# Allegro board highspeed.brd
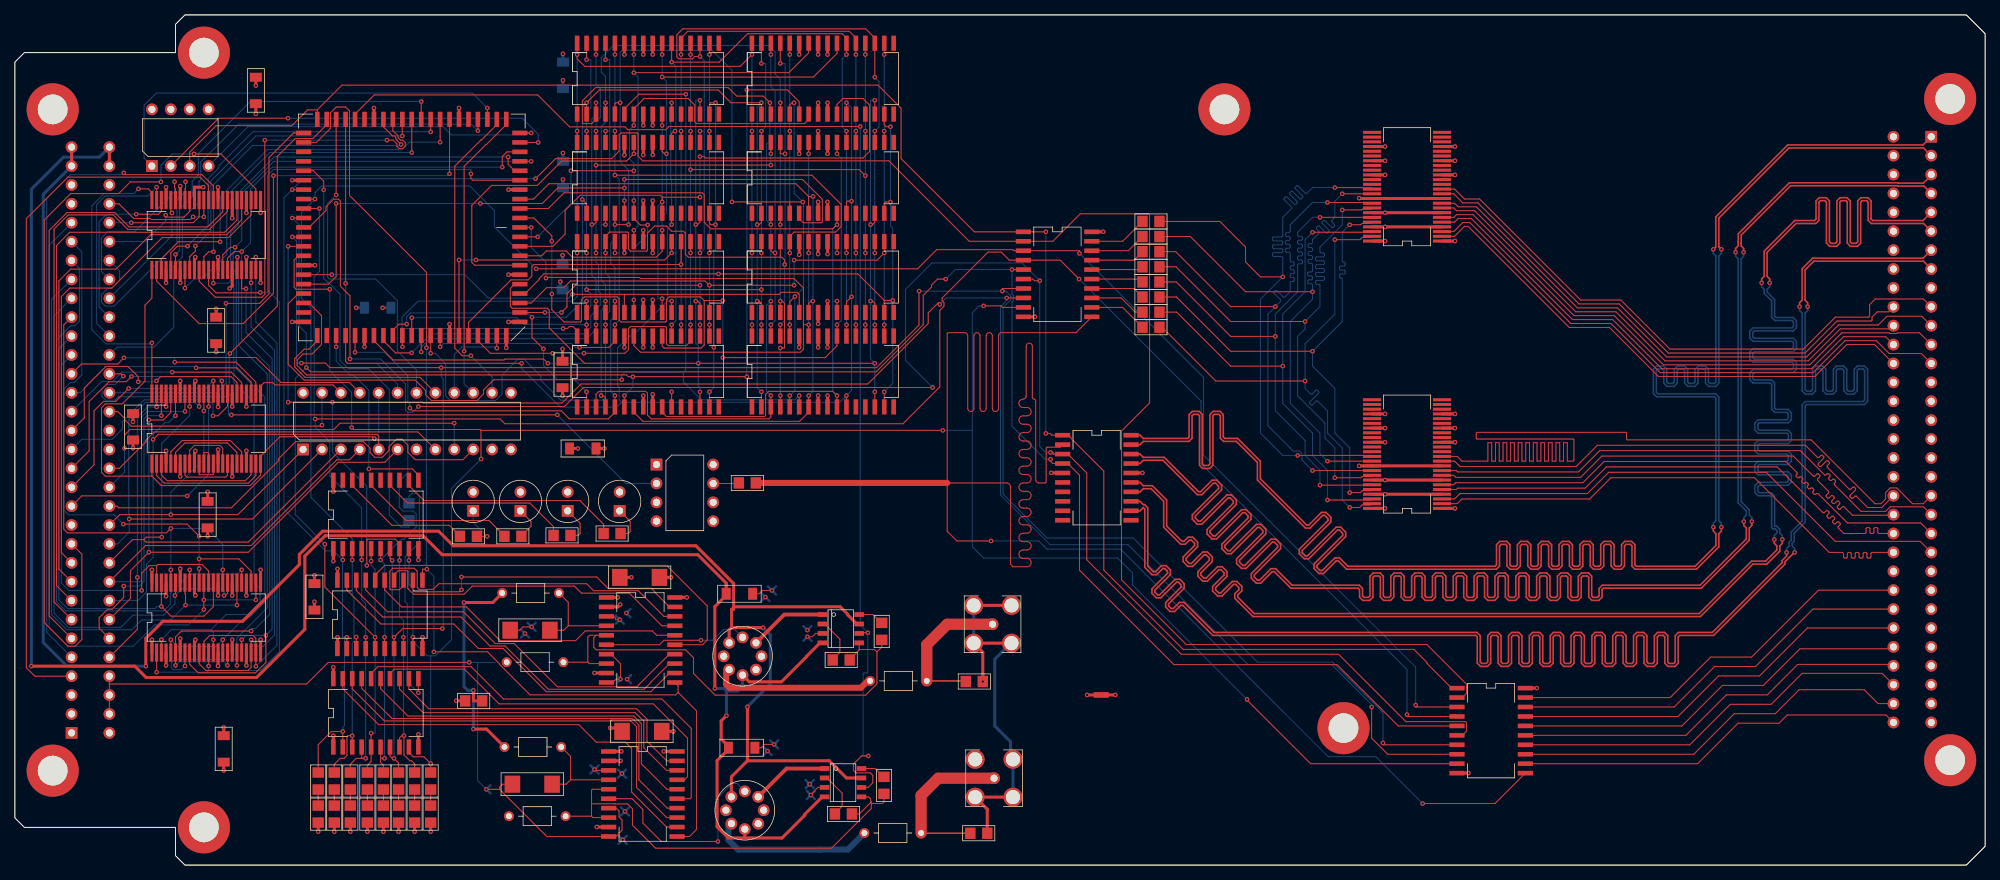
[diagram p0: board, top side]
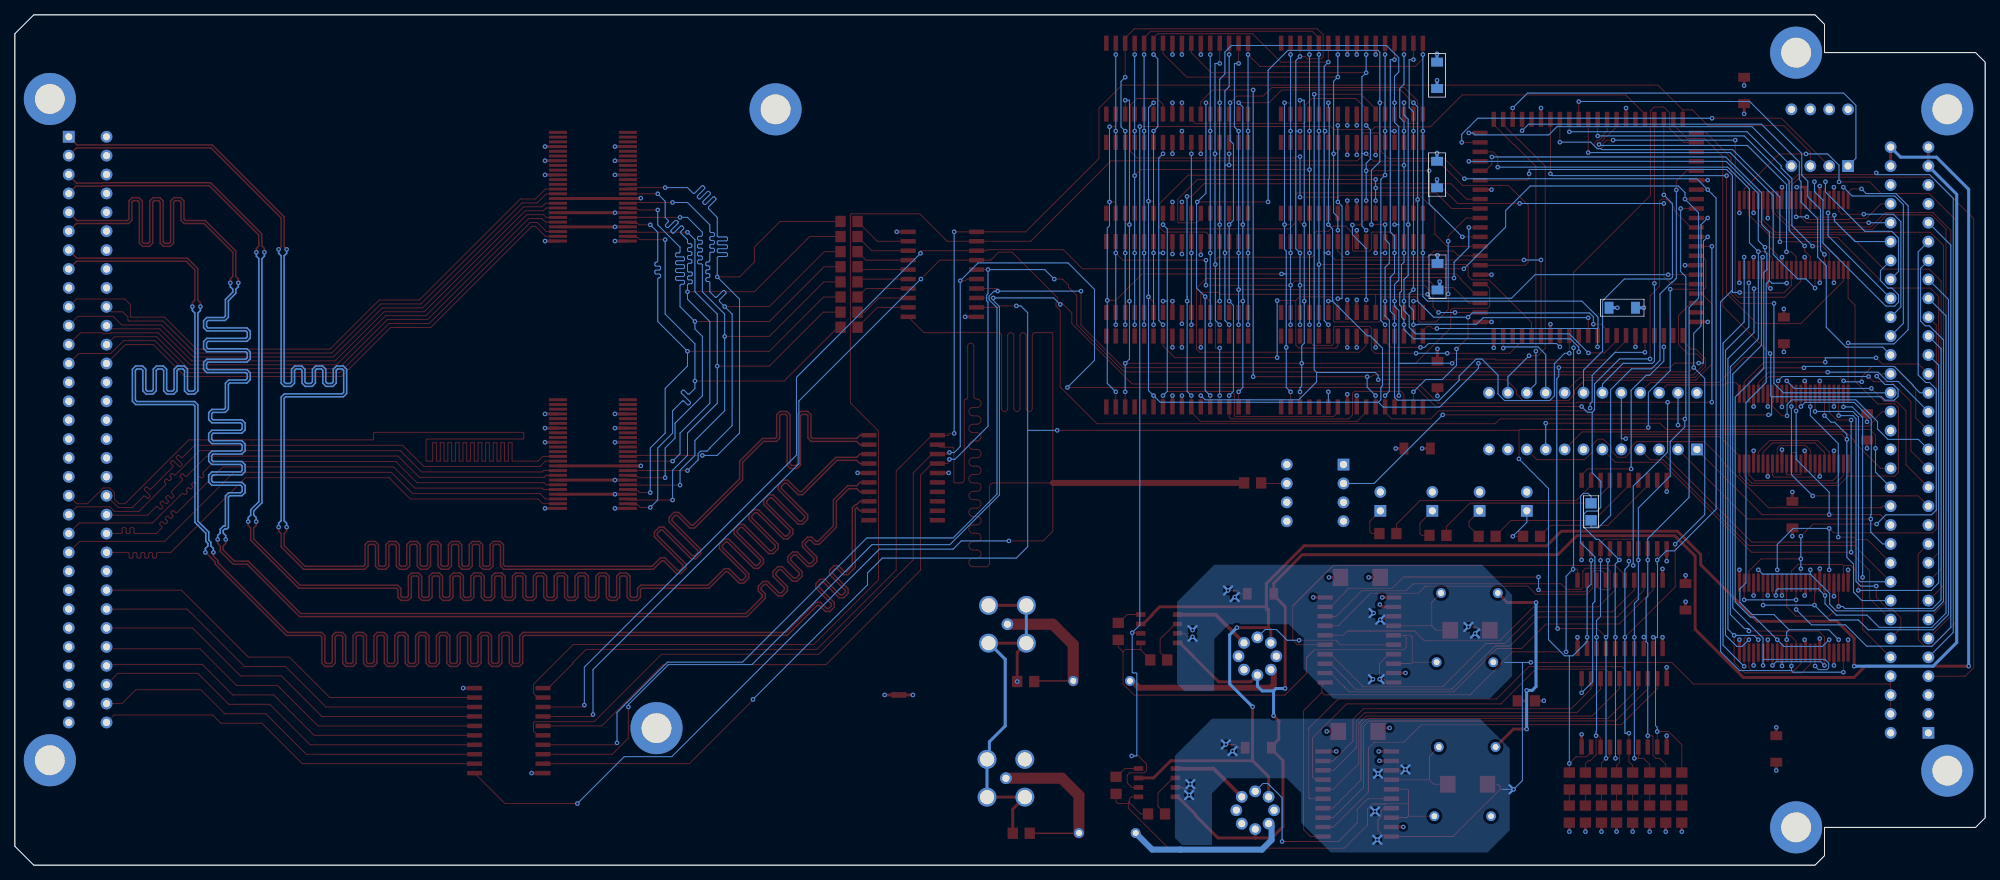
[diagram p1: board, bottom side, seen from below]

Outline 264.8 x 114.3 mm; copper layers: TOP, GND, VCC, BOTTOM. Coordinates in mm from the lower left corner of the outline.

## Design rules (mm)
constraint set DEFAULT: min track width 0.127
net group Q0: nets Q0 Q1
net group Q2: nets Q2 Q3
net group Q4: nets Q4 Q5
net group Q6: nets Q6 Q7
net group VD<0>: nets UNNAMED_1_CAP_I74_A VD<0>
net group VD<1>: nets UNNAMED_1_CAP_I73_A VD<1>
net group VD<2>: nets UNNAMED_1_CAP_I72_A VD<2>
net group VD<3>: nets UNNAMED_1_CAP_I71_A VD<3>
net group VD<4>: nets UNNAMED_1_CAP_I70_A VD<4>
net group VD<5>: nets UNNAMED_1_CAP_I69_A VD<5>
net group VD<6>: nets UNNAMED_1_CAP_I68_A VD<6>
net group VD<7>: nets UNNAMED_1_CAP_I67_A VD<7>
net group VREF: nets UNNAMED_1_CAP_I33_A_1 UNNAMED_1_CAP_I33_A_2
net group A: nets A<0> A<1> A<2> A<3> A<4> A<5> A<6> A<7> A<8> A<9> A<10> A<11> A<12> A<13> A<14> A<15> A<16> A<17> A<18> A<19> A<20> A<21> A<22> A<23>
net group BA: nets BA<0> BA<1> BA<2> BA<3> BA<4> BA<5> BA<6> BA<7>
net group BD: nets BD<0> BD<1> BD<2> BD<3> BD<4> BD<5> BD<6> BD<7> BD<8> BD<9> BD<10> BD<11> BD<12> BD<13> BD<14> BD<15>
net group BR: nets BR<0> BR<1> BR<2> BR<3> BR<4> BR<5> BR<6> BR<7>
net group CLOCKS: nets CLK1_N CLK2_N CLK3_N CLK4_N DCLK MCLK UNNAMED_2_EPF8282A_I1_VCLKC VCLKA VCLKC
net group D: nets D<0> D<1> D<2> D<3> D<4> D<5> D<6> D<7> D<8> D<9> D<10> D<11> D<12> D<13> D<14> D<15>
net group DP_CLK1: nets CLK1_P
net group DP_CLK2: nets CLK2_P
net group DP_CLK3: nets CLK3_P
net group DP_CLK4: nets CLK4_P
net group IO<0>: nets UNNAMED_3_ACT574_I6_Q0
net group IO<1>: nets UNNAMED_3_ACT574_I6_Q1
net group IO<2>: nets UNNAMED_3_ACT574_I6_Q2
net group IO<3>: nets UNNAMED_3_ACT574_I6_Q3
net group IO<4>: nets UNNAMED_3_ACT574_I6_Q4
net group IO<5>: nets UNNAMED_3_ACT574_I6_Q5
net group IO<6>: nets UNNAMED_3_ACT574_I6_Q6
net group IO<7>: nets UNNAMED_3_ACT574_I6_Q7
net group IOA: nets IOA<0> IOA<1> IOA<2> IOA<3> IOA<4> IOA<5> IOA<6> IOA<7>
net group IOB: nets IOB<0> IOB<1> IOB<2> IOB<3> IOB<4> IOB<5> IOB<6> IOB<7>
net group POWER: nets GND V12N V+12 VCC VREF
net group RA: nets RA<0> RA<1> RA<2> RA<3> RA<4> RA<5> RA<6> RA<7> RA<8> RA<9> RA<10> RA<11> RA<12> RA<13> RA<14> RA<15>
net group RD: nets RD<0> RD<1> RD<2> RD<3> RD<4> RD<5> RD<6> RD<7>
net group UNNAMED_1_DG419_I6_S1_1: nets UNNAMED_1_DG419_I6_S1_1 UNNAMED_1_DG419_I6_S2_1 UNNAMED_1_DG419_I6_VL_1
net group UNNAMED_1_DG419_I6_S1_2: nets UNNAMED_1_DG419_I6_S1_2 UNNAMED_1_DG419_I6_S2_2 UNNAMED_1_DG419_I6_VL_2

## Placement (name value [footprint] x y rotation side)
C1  .1UF  [SM_1206]  73.6 80.88 270 bottom
C1_1  .01UF  [SMC_6032]  81.3 38.68 0 top
C1_2  .01UF  [SMC_6032]  81.6 17.98 0 top
C2  .1UF  [SM_1206]  15.88 57.15 90 top
C2_1  .01UF  [SMC_6032]  71.9 31.58 180 top
C2_2  .01UF  [SMC_6032]  72.2 10.88 180 top
C3  .1UF  [SM_1206]  40.26 37.85 270 top
C3_1  .1UF  [SM_1206]  95.6 36.48 0 top
C3_2  .1UF  [SM_1206]  95.9 15.78 0 top
C4  .1UF  [SM_1206]  46.99 74.93 0 bottom
C5  .1UF  [SM_1206]  73.6 64.18 90 top
C6  .1UF  [SM_1206]  74.55 56.01 0 top
C7  .1UF  [SM_1206]  73.66 107.95 270 bottom
C8  .1UF  [SM_1206]  73.66 94.61 270 bottom
C9  47PF  [SM_0805]  127.8 24.68 0 top
C13  47PF  [SM_0805]  128.4 4.28 0 top
C17  .1UF  [SM_1206]  25.91 48.9 270 top
C18  .1UF  [SM_1206]  28.07 17.4 270 top
C19  .1UF  [SM_1206]  27.05 73.66 270 top
C20  .1UF  [SM_1206]  32.39 105.92 270 top
C21  3300PF  [SM_0805]  55.88 8 270 top
C22  3300PF  [SM_0805]  53.72 8 270 top
C23  3300PF  [SM_0805]  51.56 8 270 top
C24  3300PF  [SM_0805]  49.53 8 270 top
C25  3300PF  [SM_0805]  47.37 8 270 top
C26  3300PF  [SM_0805]  45.08 8 270 top
C27  3300PF  [SM_0805]  42.93 8 270 top
C28  3300PF  [SM_0805]  40.77 8 270 top
CR1  -  [LED]  61.59 47.62 90 top
CR2  -  [LED]  67.95 47.62 90 top
CR3  -  [LED]  74.3 47.62 90 top
CR4  -  [LED]  81.28 47.62 90 top
J1  -  [BNC]  131.4 32.38 0 top
J2  -  [BNC]  131.6 11.68 0 top
J3  -  [DIN64_HSP]  7.62 17.78 0 top
J5  -  [DIN64_HSP]  257.56 97.92 180 top
L1  50UH  [IND300]  114.94 24.77 0 top
L1_1  50UH  [IND300]  65.5 36.58 0 top
L1_2  50UH  [IND300]  65.8 15.88 0 top
L2_1  50UH  [IND300]  66.1 27.28 0 top
L2_2  50UH  [IND300]  66.4 6.58 0 top
L4  50UH  [IND300]  114.17 4.32 0 top
NOREF  -  []  -24.38 -86.28 0 top
NOREF#2  -  []  23 7.48 0 top
NOREF#3  -  [unnamed#2]  25.4 5.08 0 top
NOREF#4  -  []  13.88 164.74 0 top
R1_1  100  [SM_0805]  116.5 30.28 90 top
R1_2  100  [SM_0805]  116.8 9.58 90 top
R2_1  100  [SM_0805]  112.2 27.58 180 top
R2_2  100  [SM_0805]  112.5 6.88 180 top
R5  2K  [SM_0805]  52.96 46.36 90 bottom
R6  150  [SM_0805]  62.1 44.2 180 top
R7  150  [SM_0805]  68.07 44.2 180 top
R8  150  [SM_0805]  74.68 44.32 180 top
R9  150  [SM_0805]  81.41 44.58 180 top
R10  2K  [SM_0805]  62.8 22.08 180 top
R11  10K  [SM_0805]  55.88 12.45 270 top
R12  10K  [SM_0805]  53.72 12.45 270 top
R13  10K  [SM_0805]  51.56 12.45 270 top
R14  10K  [SM_0805]  49.53 12.45 270 top
R15  10K  [SM_0805]  47.37 12.45 270 top
R16  10K  [SM_0805]  45.08 12.45 270 top
R17  10K  [SM_0805]  42.93 12.45 270 top
R18  10K  [SM_0805]  40.77 12.45 270 top
R19  33  [SM_0805]  97.3 51.38 0 top
R20  33  [SM_0805]  151.54 86.53 0 top
R21  33  [SM_0805]  151.54 84.5 0 top
R22  33  [SM_0805]  151.54 82.47 0 top
R23  33  [SM_0805]  151.54 80.44 0 top
R24  33  [SM_0805]  151.54 78.4 0 top
R25  33  [SM_0805]  151.54 76.37 0 top
R26  33  [SM_0805]  151.54 74.34 0 top
R27  33  [SM_0805]  151.54 72.31 0 top
S1  -  [SHORT_DUMMY]  146 22.88 0 top
U1  -  [SOIC32]  75.56 74.3 90 top
U1_1  -  [SOIC20]  79.5 35.98 0 top
U1_2  -  [SOIC20]  79.8 15.28 0 top
U2  -  [SOIC32]  75.56 87.63 90 top
U2_1  ***  [SOIC8]  111 31.78 0 top
U2_2  ***  [SOIC8]  111.3 11.08 0 top
U3  -  [SOIC32]  99.06 61.6 90 top
U3_1  -  [TO-99]  97.8 28.08 90 top
U3_2  -  [TO-99]  98.1 7.38 90 top
U4  -  [SOIC32]  75.56 100.96 90 top
U5  -  [SOIC32]  75.56 61.6 90 top
U6  -  [SOIC32]  99.06 100.96 90 top
U7  -  [PLCC84]  53.34 85.72 90 top
U8  -  [SOIC20]  140.81 57.8 0 top
U14  -  [SOIC48]  18.41 53.98 90 top
U15  -  [SOIC48]  18.41 80.01 90 top
U16  -  [SOIC48]  18.41 28.57 90 top
U17  -  [DIP24]  38.73 55.88 90 top
U18  -  [DIP8]  18.41 93.98 90 top
U19  -  [SOIC20]  42.8 42.55 90 top
U20  -  [SOIC20]  43.34 29.11 90 top
U21  -  [SOIC20]  42.8 15.88 90 top
U22  -  [DIP8]  86.23 53.85 0 top
U24  -  [SOIC20]  135.54 85.13 0 top
U25  -  [SOIC20]  193.81 23.79 0 top
U26  -  [SOIC48]  191.8 83.9 180 top
U27  -  [SOIC48]  191.8 47.96 180 top
U101  -  [SOIC32]  99.06 74.3 90 top
U102  -  [SOIC32]  99.06 87.63 90 top

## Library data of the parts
C1-C8 = CAP_NP: part number: CAP_NP_SMDCAP-.1UF,+20%/-80%; signal model: cap_100n; alternate symbols: (SM_1206_REF,SM_1206_SOL); room: HIGH_SPEED_RAM
C1_1 C2_1 = CAP: part number: CAP_SMDCAP-.01UF,10%; signal model: cap_10n; alternate symbols: (SMC_6032_REF,SMC_6032_SOL); room: DAAMP1
C1_2 C2_2 = CAP: part number: CAP_SMDCAP-.01UF,10%; signal model: cap_10n; alternate symbols: (SMC_6032_REF,SMC_6032_SOL); room: DAAMP2
C3_1 = CAP_NP: part number: CAP_NP_SMDCAP-.1UF,+20%/-80%; signal model: cap_100n; alternate symbols: (SM_1206_REF,SM_1206_SOL); room: DAAMP1
C3_2 = CAP_NP: part number: CAP_NP_SMDCAP-.1UF,+20%/-80%; signal model: cap_100n; alternate symbols: (SM_1206_REF,SM_1206_SOL); room: DAAMP2
C9 = CAP: part number: CAP_SMDCAP-47PF,10%; signal model: cap_47p; alternate symbols: (SM_0805_REF,SM_0805_SOL); room: DAAMP1
C13 = CAP: part number: CAP_SMDCAP-47PF,10%; signal model: cap_47p; alternate symbols: (SM_0805_REF,SM_0805_SOL); room: DAAMP2
C17-C20 = CAP_NP: part number: CAP_NP_SMDCAP-.1UF,+20%/-80%; signal model: cap_100n; alternate symbols: (SM_1206_REF,SM_1206_SOL); room: MEM
C21 C22 = CAP: part number: CAP_SMDCAP-3300PF,10%; signal model: cap_3n3; alternate symbols: (SM_0805_REF,SM_0805_SOL); room: MEM
C23-C25 = CAP: part number: CAP_SMDCAP-3300PF,10%; signal model: cap_3n3; alternate symbols: (SM_0805_REF,SM_0805_SOL); room: DAAMP1
C26-C28 = CAP: part number: CAP_SMDCAP-3300PF,10%; signal model: cap_3n3; alternate symbols: (SM_0805_REF,SM_0805_SOL); room: DAAMP2
CR1-CR4 = PHOTO_DIODE: part number: PHOTO_DIODE_TH-BASE
J1 = BNC_CONN: part number: BNC_CONN_PCMOUNT-BASE; room: DAAMP1
J2 = BNC_CONN: part number: BNC_CONN_PCMOUNT-BASE; room: DAAMP2
J3 = CONN64_PCMOUNT-HSP: room: CONN
J5 = CONN64_PCMOUNT-HSP
L1 L1_1 L2_1 = INDUCTOR: part number: INDUCTOR_TH-50UH,5%; signal model: ind_50u; room: DAAMP1
L1_2 L2_2 L4 = INDUCTOR: part number: INDUCTOR_TH-50UH,5%; signal model: ind_50u; room: DAAMP2
R1_1 R2_1 = RES: part number: RES_SMDRES-100,2%; signal model: res_100r; alternate symbols: (SM_0805_REF,SM_0805_SOL); room: DAAMP1
R1_2 R2_2 = RES: part number: RES_SMDRES-100,2%; signal model: res_100r; alternate symbols: (SM_0805_REF,SM_0805_SOL); room: DAAMP2
R5 = RES: part number: RES_SMDRES-2K,2%; signal model: res_2k; alternate symbols: (SM_0805_REF,SM_0805_SOL)
R6-R9 = RES: part number: RES_SMDRES-150,2%; signal model: res_150r; alternate symbols: (SM_0805,SM_0805_REF,SM_0805_SOL); room: TERM
R10 = RES: part number: RES_SMDRES-2K,2%; signal model: res_2k; alternate symbols: (SM_0805_REF,SM_0805_SOL); room: TERM
R11-R13 = RES: part number: RES_SMDRES-10K,2%; signal model: res_10k; alternate symbols: (SM_0805_REF,SM_0805_SOL); room: TERM
R14 = RES: part number: RES_SMDRES-10K,2%; signal model: res_10k; alternate symbols: (SM_0805_REF,SM_0805_SOL); room: CHAN2
R15 R16 = RES: part number: RES_SMDRES-10K,2%; signal model: res_10k; alternate symbols: (SM_0805_REF,SM_0805_SOL); room: DAAMP1
R17 R18 = RES: part number: RES_SMDRES-10K,2%; signal model: res_10k; alternate symbols: (SM_0805_REF,SM_0805_SOL); room: DAAMP2
R19-R27 = RES: part number: RES_SMDRES-33,5%; signal model: res_33r; alternate symbols: (SM_0805_REF,SM_0805_SOL)
S1 = DUMMY_SHORT
U1-U6 U101 U102 = TC55B4257: part number: TC55B4257_SOIC-BASE; alternate symbols: (SOIC32_REF,SOIC32_SOL); room: HIGH_SPEED_RAM
U1_1 = TLC5602: part number: TLC5602_SOIC-BASE; alternate symbols: (SOIC20_REF,SOIC20_SOL); room: DAAMP1
U1_2 = TLC5602: part number: TLC5602_SOIC-BASE; alternate symbols: (SOIC20_REF,SOIC20_SOL); room: DAAMP2
U2_1 = DG419: User Part Number: ic303132; part number: DG419_SOIC-BASE; room: DAAMP1
U2_2 = DG419: User Part Number: ic303132; part number: DG419_SOIC-BASE; room: DAAMP2
U3_1 = TLE2037: part number: TLE2037_CAN-BASE; room: DAAMP1
U3_2 = TLE2037: part number: TLE2037_CAN-BASE; room: DAAMP2
U7 = EPF8282A: part number: EPF8282A_PLCC-BASE; room: CPU; signal model: EPF8282A_PLCC_BASE
U8 = DS90CP22: part number: DS90CP22_SOIC-BASE; signal model: ds90cp22
U14-U16 = FCT16245: part number: FCT16245_SOIC-BASE; signal model: fct16245; alternate symbols: (SOIC48_REF,SOIC48_SOL); room: CONN
U17 = 20L10: alternate symbols: (T:SOIC24;B:SOIC24_PE); part number: 20L10_DIP-BASE; room: CONN
U18 = EPC1064: part number: EPC1064_DIP-BASE
U19 U24 U25 = ACT574: alternate symbols: (SOIC20_REF,SOIC20_SOL); part number: ACT574_SOIC-BASE; signal model: act574
U20 U21 = ACT574: alternate symbols: (SOIC20_REF,SOIC20_SOL); part number: ACT574_SOIC-BASE; signal model: act574; room: MEM
U22 = MN3102: part number: MN3102_DIP-BASE; signal model: mn3102
U26 U27 = FCT16245: part number: FCT16245_SOIC-BASE; signal model: fct16245; alternate symbols: (SOIC48_REF,SOIC48_SOL)

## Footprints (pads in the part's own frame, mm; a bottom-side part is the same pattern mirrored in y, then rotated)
BNC
  round 1.575 hole 0.965: 1(0,0)
  round 2.54 hole 1.905: 2(-2.54,2.54) 3(-2.54,-2.54) 4(2.54,2.54) 5(2.54,-2.54)
DIN64_HSP
  round 7 hole 4 unplated: (-2.54,83.82) (-2.54,-5.08)
  rect 1.575x1.575 hole 0.965: 1(0,0)
  round 1.575 hole 0.965: 2(0,2.54) 3(0,5.08) 4(0,7.62) 5(0,10.16) 6(0,12.7) 7(0,15.24) 8(0,17.78) 9(0,20.32) 10(0,22.86) 11(0,25.4) 12(0,27.94) 13(0,30.48) 14(0,33.02) 15(0,35.56) 16(0,38.1) 17(0,40.64) 18(0,43.18) 19(0,45.72) 20(0,48.26) 21(0,50.8) 22(0,53.34) 23(0,55.88) 24(0,58.42) 25(0,60.96) 26(0,63.5) 27(0,66.04) 28(0,68.58) 29(0,71.12) 30(0,73.66) 31(0,76.2) 32(0,78.74) 33(5.08,0) 34(5.08,2.54) 35(5.08,5.08) 36(5.08,7.62) 37(5.08,10.16) 38(5.08,12.7) 39(5.08,15.24) 40(5.08,17.78) 41(5.08,20.32) 42(5.08,22.86) 43(5.08,25.4) 44(5.08,27.94) 45(5.08,30.48) 46(5.08,33.02) 47(5.08,35.56) 48(5.08,38.1) 49(5.08,40.64) 50(5.08,43.18) 51(5.08,45.72) 52(5.08,48.26) 53(5.08,50.8) 54(5.08,53.34) 55(5.08,55.88) 56(5.08,58.42) 57(5.08,60.96) 58(5.08,63.5) 59(5.08,66.04) 60(5.08,68.58) 61(5.08,71.12) 62(5.08,73.66) 63(5.08,76.2) 64(5.08,78.74)
DIP8
  rect 1.575x1.575 hole 0.965: 1(0,0)
  round 1.575 hole 0.965: 2(0,-2.54) 3(0,-5.08) 4(0,-7.62) 5(7.62,-7.62) 6(7.62,-5.08) 7(7.62,-2.54) 8(7.62,0)
DIP24
  rect 1.575x1.575 hole 0.965: 1(0,0)
  round 1.575 hole 0.965: 2(0,-2.54) 3(0,-5.08) 4(0,-7.62) 5(0,-10.16) 6(0,-12.7) 7(0,-15.24) 8(0,-17.78) 9(0,-20.32) 10(0,-22.86) 11(0,-25.4) 12(0,-27.94) 13(7.62,-27.94) 14(7.62,-25.4) 15(7.62,-22.86) 16(7.62,-20.32) 17(7.62,-17.78) 18(7.62,-15.24) 19(7.62,-12.7) 20(7.62,-10.16) 21(7.62,-7.62) 22(7.62,-5.08) 23(7.62,-2.54) 24(7.62,0)
IND300
  round 1.321 hole 0.787: 1(0,0) 2(7.62,0)
LED
  rect 1.575x1.575 hole 0.965: 1(0,0)
  round 1.575 hole 0.965: 2(2.54,0)
PLCC84
  rect 0.61x2.032 smd: 1(0,-14.529) 2(1.27,-14.529) 3(2.54,-14.529) 4(3.81,-14.529) 5(5.08,-14.529) 6(6.35,-14.529) 7(7.62,-14.529) 8(8.89,-14.529) 9(10.16,-14.529) 10(11.43,-14.529) 11(12.7,-14.529) 33(12.7,14.529) 34(11.43,14.529) 35(10.16,14.529) 36(8.89,14.529) 37(7.62,14.529) 38(6.35,14.529) 39(5.08,14.529) 40(3.81,14.529) 41(2.54,14.529) 42(1.27,14.529) 43(0,14.529) 44(-1.27,14.529) 45(-2.54,14.529) 46(-3.81,14.529) 47(-5.08,14.529) 48(-6.35,14.529) 49(-7.62,14.529) 50(-8.89,14.529) 51(-10.16,14.529) 52(-11.43,14.529) 53(-12.7,14.529) 75(-12.7,-14.529) 76(-11.43,-14.529) 77(-10.16,-14.529) 78(-8.89,-14.529) 79(-7.62,-14.529) 80(-6.35,-14.529) 81(-5.08,-14.529) 82(-3.81,-14.529) 83(-2.54,-14.529) 84(-1.27,-14.529)
  rect 2.032x0.61 smd: 12(14.529,-12.7) 13(14.529,-11.43) 14(14.529,-10.16) 15(14.529,-8.89) 16(14.529,-7.62) 17(14.529,-6.35) 18(14.529,-5.08) 19(14.529,-3.81) 20(14.529,-2.54) 21(14.529,-1.27) 22(14.529,0) 23(14.529,1.27) 24(14.529,2.54) 25(14.529,3.81) 26(14.529,5.08) 27(14.529,6.35) 28(14.529,7.62) 29(14.529,8.89) 30(14.529,10.16) 31(14.529,11.43) 32(14.529,12.7) 54(-14.529,12.7) 55(-14.529,11.43) 56(-14.529,10.16) 57(-14.529,8.89) 58(-14.529,7.62) 59(-14.529,6.35) 60(-14.529,5.08) 61(-14.529,3.81) 62(-14.529,2.54) 63(-14.529,1.27) 64(-14.529,0) 65(-14.529,-1.27) 66(-14.529,-2.54) 67(-14.529,-3.81) 68(-14.529,-5.08) 69(-14.529,-6.35) 70(-14.529,-7.62) 71(-14.529,-8.89) 72(-14.529,-10.16) 73(-14.529,-11.43) 74(-14.529,-12.7)
SHORT_DUMMY
  rect 1.016x0.762 smd: 1(-0.5,0) 2(0.5,0)
SM_0805
  rect 1.397x1.524 smd: 1(0,0) 2(2.286,0)
SM_1206
  rect 1.194x1.6 smd: 1(0,0) 2(3.556,0)
SMC_6032
  rect 2.083x2.286 smd: 1(0,0) 2(5.334,0)
SOIC8
  rect 1.27x0.635 smd: 1(-2.477,1.905) 2(-2.477,0.635) 3(-2.477,-0.635) 4(-2.477,-1.905) 5(2.477,-1.905) 6(2.477,-0.635) 7(2.477,0.635) 8(2.477,1.905)
SOIC20
  rect 2.032x0.61 smd: 1(0,0) 2(0,-1.27) 3(0,-2.54) 4(0,-3.81) 5(0,-5.08) 6(0,-6.35) 7(0,-7.62) 8(0,-8.89) 9(0,-10.16) 10(0,-11.43) 11(9.195,-11.43) 12(9.195,-10.16) 13(9.195,-8.89) 14(9.195,-7.62) 15(9.195,-6.35) 16(9.195,-5.08) 17(9.195,-3.81) 18(9.195,-2.54) 19(9.195,-1.27) 20(9.195,0)
SOIC32
  rect 2.032x0.61 smd: 1(0,0) 2(0,-1.27) 3(0,-2.54) 4(0,-3.81) 5(0,-5.08) 6(0,-6.35) 7(0,-7.62) 8(0,-8.89) 9(0,-10.16) 10(0,-11.43) 11(0,-12.7) 12(0,-13.97) 13(0,-15.24) 14(0,-16.51) 15(0,-17.78) 16(0,-19.05) 17(9.525,-19.05) 18(9.525,-17.78) 19(9.525,-16.51) 20(9.525,-15.24) 21(9.525,-13.97) 22(9.525,-12.7) 23(9.525,-11.43) 24(9.525,-10.16) 25(9.525,-8.89) 26(9.525,-7.62) 27(9.525,-6.35) 28(9.525,-5.08) 29(9.525,-3.81) 30(9.525,-2.54) 31(9.525,-1.27) 32(9.525,0)
SOIC48
  rect 2.438x0.406 smd: 1(0,0) 2(0,-0.635) 3(0,-1.27) 4(0,-1.905) 5(0,-2.54) 6(0,-3.175) 7(0,-3.81) 8(0,-4.445) 9(0,-5.08) 10(0,-5.715) 11(0,-6.35) 12(0,-6.985) 13(0,-7.62) 14(0,-8.255) 15(0,-8.89) 16(0,-9.525) 17(0,-10.16) 18(0,-10.795) 19(0,-11.43) 20(0,-12.065) 21(0,-12.7) 22(0,-13.335) 23(0,-13.97) 24(0,-14.605) 25(9.398,-14.605) 26(9.398,-13.97) 27(9.398,-13.335) 28(9.398,-12.7) 29(9.398,-12.065) 30(9.398,-11.43) 31(9.398,-10.795) 32(9.398,-10.16) 33(9.398,-9.525) 34(9.398,-8.89) 35(9.398,-8.255) 36(9.398,-7.62) 37(9.398,-6.985) 38(9.398,-6.35) 39(9.398,-5.715) 40(9.398,-5.08) 41(9.398,-4.445) 42(9.398,-3.81) 43(9.398,-3.175) 44(9.398,-2.54) 45(9.398,-1.905) 46(9.398,-1.27) 47(9.398,-0.635) 48(9.398,0)
TO-99
  round 1.575 hole 0.965: 1(0,-2.54) 2(1.803,-1.803) 3(2.54,0) 4(1.803,1.803) 5(0,2.54) 6(-1.803,1.803) 7(-2.54,0) 8(-1.803,-1.803)
unnamed#2
  round 7 hole 4 unplated: (0,104.14) (0,0) (137.16,96.52) (153.162,13.335)

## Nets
AGND: C2_1.2(B) C2_2.2(B) C3_1.2(B) C3_2.2(B) J3.34 J3.35 J3.36 U1_1.3 U1_1.7 U1_1.10 U1_2.3 U1_2.7 U1_2.10 U2_1.3 U2_2.3
GND: C1.2(B) C1_1.2(B) C1_2.2(B) C2.2(B) C3.2(B) C4.2(B) C5.2(B) C6.2(B) C7.2(B) C8.2(B) C17.2(B) C18.2(B) C19.2(B) C20.2(B) C21.2(B) C22.2(B) C23.2(B) C24.2(B) C25.2(B) C26.2(B) C27.2(B) C28.2(B) J3.1 J3.2 J3.3 J3.33 R10.2(B) S1.2 U1.9 U1.25 U1.27 U1_1.1 U1_1.20 U1_2.1 U1_2.20 U2.9 U2.25 U2.27 U3.9 U3.25 U3.27 U4.9 U4.25 U4.27 U5.9 U5.25 U5.27 U6.9 U6.25 U6.27 U7.5 U7.26 U7.47 U7.53 U7.68 U7.74 U7.75 U8.16 U14.7 U14.15 U14.31 U14.42 U15.7 U15.15 U15.24 U15.25 U15.31 U15.42 U16.1 U16.7 U16.15 U16.24 U16.25 U16.31 U16.42 U16.48 U17.11 U17.12 U17.13 U18.5 U19.1 U19.10 U20.1 U20.10 U21.1 U21.10 U22.4 U24.10 U25.10 U26.1 U26.7 U26.15 U26.31 U26.42 U26.48 U27.1 U27.7 U27.15 U27.31 U27.42 U27.48 U101.9 U101.25 U101.27 U102.9 U102.25 U102.27
GND_EARTH: C9.2(B) C13.2(B) J1.2 J1.3 J1.4 J1.5 J2.2 J2.3 J2.4 J2.5 S1.1
V12N: J3.31 J3.32 U2_1.7 U2_2.7 U3_1.4(V-) U3_2.4(V-)
VCC: C1.1 C1_1.1 C1_2.1 C2.1 C3.1 C4.1 C5.1 C6.1 C7.1 C8.1 C17.1 C18.1 C19.1 C20.1 CR1.2(CATHODE) CR2.2(CATHODE) CR3.2(CATHODE) CR4.2(CATHODE) J3.29 J3.30 J3.62 L2_1.1 L2_2.1 U1.8 U1.24 U1_1.2 U1_1.9(VCC2) U1_2.2 U1_2.9(VCC2) U2.8 U2.24 U3.8 U3.24 U4.8 U4.24 U5.8 U5.24 U6.8 U6.24 U7.17 U7.38 U7.59 U7.80 U8.5 U14.4 U14.10 U14.18 U14.21 U14.28 U14.34 U14.39 U14.45 U15.4 U15.10 U15.18 U15.21 U15.28 U15.34 U15.39 U15.45 U16.4 U16.10 U16.18 U16.21 U16.28 U16.34 U16.39 U16.45 U17.24 U18.7 U18.8 U19.20 U20.20 U21.20 U22.8 U24.20 U25.20 U26.4 U26.10 U26.18 U26.21 U26.28 U26.34 U26.39 U26.45 U27.4 U27.10 U27.18 U27.21 U27.28 U27.34 U27.39 U27.45 U101.8 U101.24 U102.8 U102.24
A<0>: J3.54 U15.47
A<1>: J3.55 U15.46
A<2>: J3.56 U15.44
A<3>: J3.57 U15.43
A<4>: J3.58 U15.41
A<5>: J3.59 U15.40
A<6>: J3.60 U15.38
A<7>: J3.61 U15.37
A<8>: J3.13 U14.36
A<9>: J3.14 U14.35
A<10>: J3.15 U14.33
A<11>: J3.16 U14.32
A<12>: J3.17 U14.30
A<13>: J3.18 U14.29
A<14>: J3.19 U14.27
A<15>: J3.20 U14.26
A<16>: J3.37 U14.47
A<17>: J3.38 U14.46
A<18>: J3.39 U14.44 U17.6
A<19>: J3.40 U14.43 U17.5
A<20>: J3.41 U14.41 U17.4
A<21>: J3.42 U14.40 U17.3
A<22>: J3.43 U14.38 U17.2
A<23>: J3.44 U14.37 U17.1
AEN: J3.47 U17.8
BA<0>: U7.6 U15.13(B<0>) U16.2 U16.13(B<0>)
BA<1>: U7.7 U15.14 U16.3 U16.14
BA<2>: U7.8 U15.16 U16.5 U16.16
BA<3>: U7.9 U15.17 U16.6 U16.17
BA<4>: U15.19 U16.8 U16.19
BA<5>: U15.20 U16.9 U16.20
BA<6>: U15.22 U16.11 U16.22
BA<7>: U15.23 U16.12 U16.23
BD<0>: U7.25 U15.12
BD<1>: U7.24 U15.11
BD<2>: U7.23 U15.9
BD<3>: U7.22 U15.8
BD<4>: U7.21 U15.6
BD<5>: U7.20 U15.5
BD<6>: U7.19 U15.3
BD<7>: U7.18 U15.2
BD<8>: U14.12 U14.13(B<0>)
BD<9>: U14.11 U14.14
BD<10>: U14.9 U14.16
BD<11>: U14.8 U14.17
BD<12>: U14.6 U14.19
BD<13>: U14.5 U14.20
BD<14>: U14.3 U14.22
BD<15>: U14.2 U14.23
BNC2: C9.1 J1.1(CENTER) L1.2(B)
BNC3: C13.1 J2.1(CENTER) L4.2(B)
BR<0>: J5.57 U25.19
BR<1>: J5.58 U25.18
BR<2>: J5.59 U25.17
BR<3>: J5.60 U25.16
BR<4>: J5.61 U25.15
BR<5>: J5.62 U25.14
BR<6>: J5.63 U25.13
BR<7>: J5.64 U25.12(Q7)
BRD: U7.73 U17.16
BRESET: U7.12 U17.15(O9)
BWR: U7.54 U17.17
CLK1_N: J5.2 U8.19
CLK1_P: J5.1 U8.20
CLK2_N: J5.4 U8.17
CLK2_P: J5.3 U8.18
CLK3_N: J5.6 U8.14
CLK3_P: J5.5 U8.15
CLK4_N: J5.8 U8.12
CLK4_P: J5.7 U8.13
CLOCK_IO: R19.2(B) U8.2 U24.11 U25.11
D<0>: J3.28 U16.26 U16.37
D<1>: J3.27 U16.27 U16.38
D<2>: J3.26 U16.29 U16.40
D<3>: J3.25 U16.30 U16.41
D<4>: J3.24 U16.32 U16.43
D<5>: J3.23 U16.33 U16.44
D<6>: J3.22 U16.35 U16.46
D<7>: J3.21 U16.36 U16.47
D<8>: J3.4 U15.36
D<9>: J3.5 U15.35
D<10>: J3.6 U15.33
D<11>: J3.7 U15.32
D<12>: J3.8 U15.30
D<13>: J3.9(A<9>) U15.29
D<14>: J3.10 U15.27
D<15>: J3.11 U15.26
DATA: U7.14 U18.1
DCLK: U7.10 U18.2
DDIR: U14.1 U14.24 U15.1 U17.20
DEN: U14.48 U15.48 U17.21
DHEN: U14.25 U17.22
FPGA: U7.30 U17.18
GAIN: U2_1.6 U2_2.6 U7.28
HS: U7.29 U17.19
IO<0>: R20.2(B) U26.37 U27.37
IO<1>: R21.2(B) U26.38 U27.38
IO<2>: R22.2(B) U26.40 U27.40
IO<3>: R23.2(B) U26.41 U27.41
IO<4>: R24.2(B) U26.43 U27.43
IO<5>: R25.2(B) U26.44 U27.44
IO<6>: R26.2(B) U26.46 U27.46
IO<7>: R27.2(B) U26.47 U27.47
IOA<0>: J5.45 U26.2
IOA<1>: J5.13 U26.3
IOA<2>: J5.44 U26.5
IOA<3>: J5.12 U26.6
IOA<4>: J5.43 U26.8
IOA<5>: J5.11 U26.9
IOA<6>: J5.42 U26.11
IOA<7>: J5.10 U26.12
IOB<0>: J5.55 U27.2
IOB<1>: J5.23 U27.3
IOB<2>: J5.54 U27.5
IOB<3>: J5.22 U27.6
IOB<4>: J5.53 U27.8
IOB<5>: J5.21 U27.9
IOB<6>: J5.52 U27.11
IOB<7>: J5.20 U27.12
MCLK: J3.52 U7.31 U22.2
MRD: J3.46 U17.9
MWR: J3.45 U17.10
NCS: U7.11 U18.4
OE: U7.32 U8.1 U18.3(OE) U24.1 U25.1
OUTA: L1.1 U3_1.6
OUTB: L4.1 U3_2.6
Q0: R9.2(B) U19.12(Q7)
Q1: CR4.1 R9.1
Q2: R8.2(B) U19.14
Q3: CR3.1 R8.1
Q4: R7.2(B) U19.16
Q5: CR2.1 R7.1
Q6: R6.2(B) U19.18
Q7: CR1.1 R6.1
RA<0>: U1.5 U2.5 U3.5 U4.5 U5.5 U6.5 U7.58 U101.5 U102.5
RA<1>: U1.4 U2.4 U3.4 U4.4 U5.4 U6.4 U7.60 U101.4 U102.4
RA<2>: U1.3 U2.3 U3.3 U4.3 U5.3 U6.3 U7.61 U101.3 U102.3
RA<3>: U1.2 U2.2 U3.2 U4.2 U5.2 U6.2 U7.62 U101.2 U102.2
RA<4>: U1.32 U2.32 U3.32 U4.32 U5.32 U6.32 U7.63 U101.32 U102.32
RA<5>: U1.31 U2.31 U3.31 U4.31 U5.31 U6.31 U7.64 U101.31 U102.31
RA<6>: U1.30 U2.30 U3.30 U4.30 U5.30 U6.30 U7.65 U101.30 U102.30
RA<7>: U1.29 U2.29 U3.29 U4.29 U5.29 U6.29 U7.66 U101.29 U102.29
RA<8>: U1.28 U2.28 U3.28 U4.28 U5.28 U6.28 U7.67 U101.28 U102.28
RA<9>: U1.22 U2.22 U3.22 U4.22 U5.22 U6.22 U7.69 U101.22 U102.22
RA<10>: U1.21 U2.21 U3.21 U4.21 U5.21 U6.21 U7.70 U101.21 U102.21
RA<11>: U1.20 U2.20 U3.20 U4.20 U5.20 U6.20 U7.71 U101.20 U102.20
RA<12>: U1.19 U2.19 U3.19 U4.19 U5.19 U6.19 U7.76 U101.19 U102.19
RA<13>: U1.18 U2.18 U3.18 U4.18 U5.18 U6.18 U7.77 U101.18 U102.18
RA<14>: U1.15 U2.15 U3.15 U4.15 U5.15 U6.15 U7.78 U101.15 U102.15
RA<15>: U1.14 U2.14 U3.14 U4.14 U5.14 U6.14 U7.79 U101.14 U102.14
RCS0: U1.6 U7.48 U101.6
RCS1: U2.6 U7.49 U102.6
RCS2: U3.6 U4.6 U7.50
RCS3: U5.6 U6.6 U7.51
RD<0>: U1.26 U2.26 U4.26 U6.26 U7.81
RD<1>: U1.23 U2.23 U4.23 U6.23 U7.82
RD<2>: U1.10 U2.10 U4.10 U6.10 U7.83
RD<3>: U1.7 U2.7 U4.7 U6.7 U7.84
RD<4>: U3.26 U5.26 U7.1 U101.26 U102.26
RD<5>: U3.23 U5.23 U7.2 U101.23 U102.23
RD<6>: U3.10 U5.10 U7.3 U101.10 U102.10
RD<7>: U3.7 U5.7 U7.4 U101.7 U102.7
RDY: J3.50 U17.23
RESET: J3.53 U7.15
RWE: U1.11(WE*) U2.11(WE*) U3.11(WE*) U4.11(WE*) U5.11(WE*) U6.11(WE*) U7.57 U101.11(WE*) U102.11(WE*)
SEL: U7.13 U17.14
UNNAMED_1_ACT574_I1_Q0: U1_1.12 U20.19
UNNAMED_1_ACT574_I1_Q1: U1_1.13 U20.18
UNNAMED_1_ACT574_I1_Q2: U1_1.14 U20.17
UNNAMED_1_ACT574_I1_Q3: U1_1.15 U20.16
UNNAMED_1_ACT574_I1_Q4: U1_1.16 U20.15
UNNAMED_1_ACT574_I1_Q5: U1_1.17 U20.14
UNNAMED_1_ACT574_I1_Q6: U1_1.18 U20.13
UNNAMED_1_ACT574_I1_Q7: U1_1.19 U20.12(Q7)
UNNAMED_1_ACT574_I2_Q0: U1_2.12 U21.19
UNNAMED_1_ACT574_I2_Q1: U1_2.13 U21.18
UNNAMED_1_ACT574_I2_Q2: U1_2.14 U21.17
UNNAMED_1_ACT574_I2_Q3: U1_2.15 U21.16
UNNAMED_1_ACT574_I2_Q4: U1_2.16 U21.15
UNNAMED_1_ACT574_I2_Q5: U1_2.17 U21.14
UNNAMED_1_ACT574_I2_Q6: U1_2.18 U21.13
UNNAMED_1_ACT574_I2_Q7: U1_2.19 U21.12(Q7)
UNNAMED_1_CAP_I33_A_1: C2_1.1 L1_1.2(B) U1_1.4
UNNAMED_1_CAP_I33_A_2: C2_2.1 L1_2.2(B) U1_2.4
UNNAMED_1_CAP_I67_A: C21.1 R11.2(B)
UNNAMED_1_CAP_I68_A: C22.1 R12.2(B)
UNNAMED_1_CAP_I69_A: C23.1 R13.2(B)
UNNAMED_1_CAP_I70_A: C24.1 R14.2(B)
UNNAMED_1_CAP_I71_A: C25.1 R15.2(B)
UNNAMED_1_CAP_I72_A: C26.1 R16.2(B)
UNNAMED_1_CAP_I73_A: C27.1 R17.2(B)
UNNAMED_1_CAP_I74_A: C28.1 R18.2(B)
UNNAMED_1_DG419_I6_D_1: U2_1.1 U3_1.2
UNNAMED_1_DG419_I6_D_2: U2_2.1 U3_2.2
UNNAMED_1_DG419_I6_S1_1: R2_1.2(B) U2_1.2
UNNAMED_1_DG419_I6_S1_2: R2_2.2(B) U2_2.2
UNNAMED_1_DG419_I6_S2_1: R1_1.2(B) U2_1.8
UNNAMED_1_DG419_I6_S2_2: R1_2.2(B) U2_2.8
UNNAMED_1_DG419_I6_VL_1: L2_1.2(B) R1_1.1 R2_1.1 U1_1.5 U1_1.8 U2_1.5(VL)
UNNAMED_1_DG419_I6_VL_2: L2_2.2(B) R1_2.1 R2_2.1 U1_2.5 U1_2.8 U2_2.5(VL)
UNNAMED_1_TLC5602_I31_AOUT_1: U1_1.6 U3_1.3
UNNAMED_1_TLC5602_I31_AOUT_2: U1_2.6 U3_2.3
UNNAMED_2_EPF8282A_I1_VCLKC: R5.1 U7.37
UNNAMED_3_ACT574_I6_Q0: R20.1 U24.19
UNNAMED_3_ACT574_I6_Q1: R21.1 U24.18
UNNAMED_3_ACT574_I6_Q2: R22.1 U24.17
UNNAMED_3_ACT574_I6_Q3: R23.1 U24.16
UNNAMED_3_ACT574_I6_Q4: R24.1 U24.15
UNNAMED_3_ACT574_I6_Q5: R25.1 U24.14
UNNAMED_3_ACT574_I6_Q6: R26.1 U24.13
UNNAMED_3_ACT574_I6_Q7: R27.1 U24.12(Q7)
UNNAMED_3_MN3102_I89_OUT: R19.1 U22.7(OUT)
V+12: C3_1.1 C3_2.1 J3.63 J3.64 U2_1.4 U2_2.4 U3_1.7 U3_2.7
VCLKA: U1_1.11 U1_2.11 U7.34 U20.11
VCLKC: R5.2(B) U21.11
VD<0>: R18.1 U7.39 U19.2 U20.2 U21.2 U24.2 U25.2
VD<1>: R17.1 U7.40 U19.3 U20.3 U21.3 U24.3 U25.3
VD<2>: R16.1 U7.41 U19.4 U20.4 U21.4 U24.4 U25.4
VD<3>: R15.1 U7.42 U8.4 U19.5 U20.5 U21.5 U24.5 U25.5
VD<4>: R14.1 U7.43 U8.3(SEL1) U19.6 U20.6 U21.6 U24.6 U25.6
VD<5>: R13.1 U7.44 U19.7 U20.7 U21.7 U24.7 U25.7
VD<6>: R12.1 U7.45 U19.8 U20.8 U21.8 U24.8 U25.8
VD<7>: R11.1 U7.46(VD<7>) U19.9 U20.9 U21.9 U24.9 U25.9
VREF: L1_1.1 L1_2.1 R10.1
WAIT: J3.51 U7.33
WSTAT: U7.56 U19.11

Pads without a net: J3 12 48 49; J5 9 14 15 16 17 18 19 24 25 26 27 28 29 30 31 32 33 34 35 36 37 38 39 40 41 46 47 48 49 50 51 56; U1 1 12 13 16 17; U2 1 12 13 16 17; U3 1 12 13 16 17; U3_1 1 5 8; U3_2 1 5 8; U4 1 12 13 16 17; U5 1 12 13 16 17; U6 1 12 13 16 17; U7 16 27 35 36 52 55 72; U8 6 7 8 9 10 11; U17 7; U18 6; U19 13 15 17 19; U22 1 3 5 6; U26 13 14 16 17 19 20 22 23 24 25 26 27 29 30 32 33 35 36; U27 13 14 16 17 19 20 22 23 24 25 26 27 29 30 32 33 35 36; U101 1 12 13 16 17; U102 1 12 13 16 17

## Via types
v1: diameter 0.61, hole 0.33, TOP to BOTTOM, 677 vias

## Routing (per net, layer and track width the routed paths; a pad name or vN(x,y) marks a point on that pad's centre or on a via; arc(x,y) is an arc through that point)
AGND: length 173.2
  TOP w0.127: 12.7,24.35 J3.35 J3.34 ; 12.7,24.35 39.21,24.35 42.12,27.25 v1(61.06,27.25) ; 12.7,24.35 J3.36 ; C3_2.2 100.32,15.78 100.76,16.22 v1(102.04,16.22) ; U1_2.7 80.82,7.66 81.2,7.28 81.2,6.48 81.6,6.08 81.6,4.68 80.77,3.85 U1_2.10 71.48,3.85 65.15,10.18 ; U1_2.3 78.02,12.74 v1(77.9,12.86) ; 108.82,10.45 107.92,10.45 106.98,9.51 v1(106.98,9.42) ; v1(69.44,32.02) 68.31,32.02 67.87,31.58 C2_1.2 ; v1(106.52,30.7) 107.17,30.7 107.62,31.14 U2_1.3 ; v1(63.37,10.18) 65.15,10.18 ; 65.15,10.18 65.15,10.48 65.55,10.88 C2_2.2 ; U1_1.10 80.4,24.55 80.4,24.6 80.8,24.99 v1(81.39,24.99) 81.39,27.09 80.12,28.36 U1_1.7 ; v1(101.74,36.92) 100.46,36.92 100.02,36.48 C3_1.2 ; U1_1.3 80.47,33.44 80.73,33.19 80.73,33 v1(81.3,33)
  BOTTOM w0.127: 64.87,10.18 v1(63.37,10.18) 62.19,11.37 62.19,27.25 ; 62.19,27.25 v1(61.06,27.25) ; 62.19,27.25 64.57,27.25
  BOTTOM w0.3: 81.04,11.74 v1(81.6,12.3) ; v1(81.6,12.3) 81.04,12.85 ; v1(81.6,12.3) 82.15,12.85 ; v1(81.6,12.3) 82.15,11.74 ; v1(106.82,10.89) 107.37,10.34 ; v1(106.82,10.89) 106.27,10.34 ; v1(106.82,10.89) 106.27,11.44 ; v1(106.82,10.89) 107.37,11.44 ; 100.6,15.89 v1(101.16,15.34) ; v1(101.16,15.34) 100.6,14.78 ; v1(101.16,15.34) 101.71,14.78 ; 81.13,3.96 v1(81.69,3.41) ; v1(81.69,3.41) 82.24,3.96 ; v1(81.69,3.41) 81.13,2.85 ; v1(81.69,3.41) 82.24,2.85 ; v1(100.86,36.04) 101.41,35.48 ; v1(100.86,36.04) 100.3,35.48 ; v1(100.86,36.04) 100.3,36.59 ; 63.92,9.63 v1(63.37,10.18) 63.92,10.74 ; v1(77.9,12.86) 78.46,13.41 ; v1(77.9,12.86) 78.46,12.31 ; v1(77.9,12.86) 77.35,13.41 ; v1(77.9,12.86) 77.35,12.31 ; 80.83,25.55 v1(81.39,24.99) 80.83,24.44 ; 101.19,37.48 v1(101.74,36.92) ; v1(101.74,36.92) 102.3,36.37 ; v1(101.74,36.92) 102.3,37.48 ; 68,31.69 v1(68.56,31.14) ; v1(68.56,31.14) 69.11,30.58 ; v1(68.56,31.14) 68,30.58 ; 82.83,24.44 v1(82.27,24.99) 82.83,25.55 ; 80.74,33.55 v1(81.3,33) ; v1(81.3,33) 81.85,32.44 ; v1(81.3,33) 80.74,32.44 ; v1(106.98,9.42) 107.53,9.97 ; v1(106.98,9.42) 107.53,8.87 ; v1(106.98,9.42) 106.43,9.97 ; v1(106.98,9.42) 106.43,8.87 ; v1(81.99,7.22) 82.54,7.77 ; v1(81.99,7.22) 82.54,6.66 ; v1(81.99,7.22) 81.44,7.77 ; v1(81.99,7.22) 81.44,6.66 ; v1(69.44,32.02) 70,32.58 ; v1(69.44,32.02) 68.89,32.58 ; v1(69.44,32.02) 70,31.47 ; v1(102.04,16.22) 102.6,15.67 ; v1(102.04,16.22) 102.6,16.78 ; v1(102.04,16.22) 101.49,16.78 ; 107.07,32.14 v1(106.52,31.59) 105.97,32.14 ; 105.97,30.15 v1(106.52,30.7) 107.07,30.15 ; 82.74,34.44 v1(82.18,33.88) 82.74,33.33
GND: length 505.8
  TOP w0.2: U1_1.20 89.43,35.99
  TOP w0.4: v1(109.22,89.15) U102.9 ; v1(54.23,41.02) U19.10 ; U20.10 54.77,29.82 54.79,29.83 v1(54.79,30.63) ; U27.48 183.42,47.96 v1(184.15,47.96) ; R10.2 60.51,22.1 v1(59.31,22.1) ; U27.1 192.82,47.96 192.82,47.96 v1(193.55,47.96) ; v1(81.5,15.29) 80.13,15.29 80.12,15.28 U1_2.1 ; v1(22.22,65.1) U14.42 ; U20.1 43.34,29.82 43.36,29.83 v1(43.36,30.63) ; v1(42.93,4.5) C27.2 ; v1(73.61,69.39) 73.61,67.74 C5.2 ; v1(42.8,40.87) U19.1 ; U27.31 183.42,58.75 183.42,58.75 v1(184.15,58.75) ; v1(84.45,95.48) U2.25 ; v1(184.15,83.9) 183.42,83.9 183.42,83.9 U26.48 ; v1(85.73,99.44) U4.9 ; v1(66.34,90.8) U7.5 ; v1(107.95,82.14) U101.25 ; v1(81.92,108.97) 81.92,110.49 ; v1(47.37,4.5) C25.2 ; v1(193.55,56.85) 192.82,56.85 192.82,56.85 U27.15 ; U27.7 184.15,51.77 v1(184.15,51.77) 184.15,51.77 U27.42 ; v1(33.02,39.7) U16.25 ; v1(107.95,98.68) U102.25 ; v1(27.3,55.86) U14.15 ; U26.42 184.15,87.71 v1(184.15,87.71) 184.15,87.71 U26.7 ; v1(105.41,82.04) U101.27 ; v1(40.26,35.41) C3.2 ; v1(79.22,56.01) C6.2 ; S1.2 v1(147.9,22.88) ; C1_1.2 86.63,38.68 v1(88.19,38.68) ; v1(84.45,69.6) U5.25 ; v1(109.22,75.82) U101.9 ; v1(40.33,80.64) U7.47 ; U25.10 194.53,12.36 194.53,12.37 v1(195.35,12.37) ; v1(42.8,17.4) U21.1 ; v1(27.3,26.77) U16.15 ; v1(58.42,72.72) U7.68 ; v1(33.02,78.28) U15.24 ; v1(109.22,102.49) U6.9 ; v1(45.08,4.5) C26.2 ; v1(54.23,17.58) U21.10 ; v1(105.41,108.97) U6.27 ; v1(22.22,39.85) U16.42 ; U26.1 192.82,83.9 192.82,83.9 v1(193.55,83.9) ; U26.15 192.82,92.79 192.82,92.79 v1(193.55,92.79) ; v1(85.73,89.33) U2.9 ; v1(90.3,35.99) 88.62,35.99 88.61,35.98 88.29,35.98 ; v1(29.21,61.65) U14.31 ; v1(151.54,52.73) 150.74,52.73 150.72,52.72 U8.16 ; v1(33.02,87.68) U15.25 ; v1(32.39,100.99) C20.2 ; v1(81.92,82.3) 81.92,83.82 ; v1(29.21,86.97) U15.31 ; v1(22.22,91.29) U15.42 ; v1(81.92,95.45) 81.92,97.16 ; v1(107.95,108.97) U6.25 ; v1(85.73,76) U1.9 ; v1(53.72,4.5) C22.2 ; U1_1.1 79.82,35.98 79.83,35.99 v1(81.02,35.99) ; v1(81.92,69.6) 81.92,71.12 ; v1(85.73,63.3) U5.9 ; U24.10 136.25,73.7 136.26,73.71 v1(137.08,73.71) ; v1(25.91,44.22) C17.2 ; v1(22.22,78.28) U15.7 ; 88.59,15.28 88.27,15.28 88.26,15.29 v1(87.2,15.29) ; U26.31 183.42,94.69 v1(184.15,94.69) ; v1(66.04,69.55) U7.74 ; C1_2.2 86.93,17.98 v1(88.49,17.98) ; v1(18.41,30.3) U16.1 ; v1(55.88,4.5) C21.2 ; v1(27.3,81.74) U15.15 ; v1(107.95,69.6) U3.25 ; v1(51.56,4.5) C23.2 ; v1(66.34,73.02) U7.75 ; v1(33.02,30.3) U16.24 ; v1(84.45,108.97) U4.25 ; v1(40.77,4.5) C28.2 ; v1(49.53,4.5) C24.2 ; v1(22.22,30.45) U16.7 ; v1(105.41,69.6) U3.27 ; v1(48.26,101.78) U7.26 ; v1(105.41,95.63) U102.27 ; v1(37.29,73.02) U7.53 ; v1(84.45,85.34) U1.25 ; v1(18.41,39.7) U16.48 ; v1(109.22,63.12) U3.9 ; v1(29.21,36.25) U16.31 ; v1(22.22,52.25) U14.7 ; v1(27.05,68.99) C19.2 ; v1(28.07,12.73) 28.07,13.84 ; v1(15.88,59.59) C2.2
  GND w0.3: v1(81.5,15.29) 82.05,14.74 ; v1(81.5,15.29) 82.05,15.84 ; v1(81.5,15.29) 80.95,14.74 ; v1(81.5,15.29) 80.95,15.84 ; 107.4,69.04 v1(107.95,69.6) ; v1(107.95,69.6) 108.5,69.04 ; v1(107.95,69.6) 107.4,70.15 ; v1(107.95,69.6) 108.5,70.15 ; v1(54.79,30.63) 55.34,30.08 ; v1(54.79,30.63) 54.24,30.08 ; v1(54.79,30.63) 54.24,31.18 ; v1(54.79,30.63) 55.34,31.18 ; v1(193.55,83.9) 194.1,84.45 ; v1(193.55,83.9) 193,83.34 ; v1(193.55,83.9) 194.1,83.34 ; v1(193.55,83.9) 193,84.45 ; v1(42.8,17.4) 43.35,16.85 ; v1(42.8,17.4) 43.35,17.95 ; v1(42.8,17.4) 42.25,16.85 ; v1(42.8,17.4) 42.25,17.95 ; 36.73,73.58 v1(37.29,73.02) ; v1(37.29,73.02) 37.84,73.58 ; v1(37.29,73.02) 37.84,72.47 ; v1(37.29,73.02) 36.73,72.47 ; 87.64,39.24 v1(88.19,38.68) ; v1(88.19,38.68) 88.74,39.24 ; v1(88.19,38.68) 88.74,38.13 ; v1(88.19,38.68) 87.64,38.13 ; 183.6,52.32 v1(184.15,51.77) ; v1(184.15,51.77) 183.6,51.21 ; v1(184.15,51.77) 184.7,52.32 ; v1(184.15,51.77) 184.7,51.21 ; 63.21,56.81 U17.11 ; U17.11 65.06,56.81 ; U17.11 65.06,54.95 ; 28.66,86.42 v1(29.21,86.97) ; v1(29.21,86.97) 29.76,86.42 ; v1(29.21,86.97) 28.66,87.52 ; v1(29.21,86.97) 29.76,87.52 ; 44.53,5.05 v1(45.08,4.5) ; v1(45.08,4.5) 45.64,5.05 ; v1(45.08,4.5) 44.53,3.94 ; v1(45.08,4.5) 45.64,3.94 ; 53.68,40.47 v1(54.23,41.02) ; v1(54.23,41.02) 54.78,40.47 ; v1(54.23,41.02) 54.78,41.57 ; v1(54.23,41.02) 53.68,41.57 ; 53.17,5.05 v1(53.72,4.5) ; v1(53.72,4.5) 53.17,3.94 ; v1(53.72,4.5) 54.27,5.05 ; v1(53.72,4.5) 54.27,3.94 ; v1(84.45,108.97) 85.01,108.41 ; v1(84.45,108.97) 83.9,108.41 ; v1(84.45,108.97) 83.9,109.52 ; v1(84.45,108.97) 85.01,109.52 ; 32.47,87.13 v1(33.02,87.68) ; v1(33.02,87.68) 33.57,88.23 ; v1(33.02,87.68) 32.47,88.23 ; v1(33.02,87.68) 33.57,87.13 ; 108.67,101.94 v1(109.22,102.49) ; v1(109.22,102.49) 108.67,103.04 ; v1(109.22,102.49) 109.77,103.04 ; v1(109.22,102.49) 109.77,101.94 ; 86.65,14.74 v1(87.2,15.29) ; v1(87.2,15.29) 86.65,15.84 ; v1(87.2,15.29) 87.75,15.84 ; v1(87.2,15.29) 87.75,14.74 ; v1(184.15,83.9) 184.7,84.45 ; v1(184.15,83.9) 184.7,83.34 ; v1(184.15,83.9) 183.6,84.45 ; v1(184.15,83.9) 183.6,83.34 ; J3.2 8.55,19.39 ; J3.2 8.55,21.25 ; J3.2 6.69,21.25 ; J3.2 6.69,19.39 ; 85.17,62.75 v1(85.73,63.3) ; v1(85.73,63.3) 86.28,63.85 ; v1(85.73,63.3) 85.17,63.85 ; v1(85.73,63.3) 86.28,62.75 ; v1(55.88,4.5) 56.43,3.94 ; v1(55.88,4.5) 55.33,5.05 ; v1(55.88,4.5) 56.43,5.05 ; v1(55.88,4.5) 55.33,3.94 ; v1(59.31,22.1) 59.86,22.65 ; v1(59.31,22.1) 58.76,22.65 ; v1(59.31,22.1) 59.86,21.55 ; v1(59.31,22.1) 58.76,21.55 ; 48.88,74.38 v1(49.43,74.93) ; v1(49.43,74.93) 48.88,75.48 ; v1(49.43,74.93) 49.98,74.38 ; v1(49.43,74.93) 49.98,75.48 ; 57.87,72.17 v1(58.42,72.72) ; v1(58.42,72.72) 57.87,73.27 ; v1(58.42,72.72) 58.97,73.27 ; v1(58.42,72.72) 58.97,72.17 ; 108.67,88.6 v1(109.22,89.15) ; v1(109.22,89.15) 108.67,89.71 ; v1(109.22,89.15) 109.77,89.71 ; v1(109.22,89.15) 109.77,88.6 ; v1(43.36,30.63) 43.91,31.18 ; v1(43.36,30.63) 42.81,30.08 ; v1(43.36,30.63) 42.81,31.18 ; v1(43.36,30.63) 43.91,30.08 ; v1(66.04,69.55) 66.59,68.99 ; v1(66.04,69.55) 66.59,70.1 ; v1(66.04,69.55) 65.49,68.99 ; v1(66.04,69.55) 65.49,70.1 ; v1(88.49,17.98) 89.05,18.54 ; v1(88.49,17.98) 87.94,18.54 ; v1(88.49,17.98) 87.94,17.43 ; v1(88.49,17.98) 89.05,17.43 ; v1(49.53,4.5) 50.08,5.05 ; v1(49.53,4.5) 48.98,5.05 ; v1(49.53,4.5) 48.98,3.94 ; v1(49.53,4.5) 50.08,3.94 ; v1(15.88,59.59) 16.43,59.04 ; v1(15.88,59.59) 15.32,60.14 ; v1(15.88,59.59) 16.43,60.14 ; v1(15.88,59.59) 15.32,59.04 ; 28.66,36.8 v1(29.21,36.25) ; v1(29.21,36.25) 29.76,36.8 ; v1(29.21,36.25) 29.76,35.69 ; v1(29.21,36.25) 28.66,35.69 ; v1(81.92,69.6) 82.47,70.15 ; v1(81.92,69.6) 81.36,70.15 ; v1(81.92,69.6) 82.47,69.04 ; v1(81.92,69.6) 81.36,69.04 ; v1(84.45,85.34) 85.01,84.79 ; v1(84.45,85.34) 83.9,84.79 ; v1(84.45,85.34) 83.9,85.9 ; v1(81.92,108.97) 82.47,108.41 ; v1(81.92,108.97) 81.36,109.52 ; v1(81.92,108.97) 82.47,109.52 ; v1(81.92,108.97) 81.36,108.41 ; 39.71,34.86 v1(40.26,35.41) ; v1(40.26,35.41) 39.71,35.96 ; v1(40.26,35.41) 40.81,34.86 ; v1(40.26,35.41) 40.81,35.96 ; v1(47.37,4.5) 47.92,5.05 ; v1(47.37,4.5) 47.92,3.94 ; v1(47.37,4.5) 46.82,5.05 ; v1(47.37,4.5) 46.82,3.94 ; 65.79,73.58 v1(66.34,73.02) ; v1(66.34,73.02) 66.9,72.47 ; v1(66.34,73.02) 65.79,72.47 ; v1(66.34,73.02) 66.9,73.58 ; 21.67,64.55 v1(22.22,65.1) ; v1(22.22,65.1) 22.78,64.55 ; v1(22.22,65.1) 21.67,65.65 ; v1(22.22,65.1) 22.78,65.65 ; 193,92.23 v1(193.55,92.79) ; v1(193.55,92.79) 194.1,92.23 ; v1(193.55,92.79) 193,93.34 ; v1(193.55,92.79) 194.1,93.34 ; 42.37,3.94 v1(42.93,4.5) ; v1(42.93,4.5) 43.48,5.05 ; v1(42.93,4.5) 43.48,3.94 ; v1(42.93,4.5) 42.37,5.05 ; 85.17,99.99 v1(85.73,99.44) ; v1(85.73,99.44) 86.28,98.89 ; v1(85.73,99.44) 86.28,99.99 ; v1(85.73,99.44) 85.17,98.89 ; 21.67,51.7 v1(22.22,52.25) ; v1(22.22,52.25) 22.78,52.8 ; v1(22.22,52.25) 22.78,51.7 ; v1(22.22,52.25) 21.67,52.8 ; v1(81.92,95.45) 82.47,96 ; v1(81.92,95.45) 81.36,96 ; v1(81.92,95.45) 81.36,94.9 ; v1(81.92,95.45) 82.47,94.9 ; v1(40.33,80.64) 40.89,80.09 ; v1(40.33,80.64) 40.89,81.2 ; v1(40.33,80.64) 39.78,80.09 ; v1(40.33,80.64) 39.78,81.2 ; v1(28.07,12.73) 28.62,13.28 ; v1(28.07,12.73) 28.62,12.17 ; v1(28.07,12.73) 27.52,12.17 ; v1(28.07,12.73) 27.52,13.28 ; U17.13 67.6,64.43 ; U17.13 65.75,62.57 ; U17.13 65.75,64.43 ; U17.13 67.6,62.57 ; v1(105.41,82.04) 105.96,82.59 ; v1(105.41,82.04) 104.86,82.59 ; v1(105.41,82.04) 105.96,81.49 ; 72.75,77.88 v1(73.3,78.44) ; v1(73.3,78.44) 73.86,78.99 ; v1(73.3,78.44) 73.86,77.88 ; v1(73.3,78.44) 72.75,78.99 ; v1(90.3,35.99) 90.85,35.44 ; v1(90.3,35.99) 89.75,35.44 ; v1(90.3,35.99) 90.85,36.54 ; v1(90.3,35.99) 89.75,36.54 ; 65.75,54.95 U17.12 ; U17.12 65.75,56.81 ; U17.12 67.6,54.95 ; U17.12 67.6,56.81 ; v1(73.66,105.51) 74.21,104.96 ; v1(73.66,105.51) 73.11,106.06 ; v1(73.66,105.51) 74.21,106.06 ; v1(73.66,105.51) 73.11,104.96 ; v1(73.61,69.39) 74.16,68.84 ; v1(73.61,69.39) 74.16,69.94 ; v1(73.61,69.39) 73.06,69.94 ; v1(73.61,69.39) 73.06,68.84 ; 26.75,26.22 v1(27.3,26.77) ; v1(27.3,26.77) 27.86,26.22 ; v1(27.3,26.77) 27.86,27.32 ; v1(27.3,26.77) 26.75,27.32 ; v1(107.95,108.97) 108.5,108.41 ; v1(107.95,108.97) 107.4,109.52 ; v1(107.95,108.97) 108.5,109.52 ; v1(107.95,108.97) 107.4,108.41 ; v1(151.54,52.73) 152.09,52.18 ; v1(151.54,52.73) 152.09,53.28 ; v1(151.54,52.73) 150.98,53.28 ; v1(151.54,52.73) 150.98,52.18 ; 108.67,62.57 v1(109.22,63.12) ; v1(109.22,63.12) 108.67,63.67 ; v1(109.22,63.12) 109.77,62.57 ; v1(109.22,63.12) 109.77,63.67 ; 183.6,48.51 v1(184.15,47.96) ; v1(184.15,47.96) 184.7,48.51 ; v1(184.15,47.96) 183.6,47.4 ; v1(184.15,47.96) 184.7,47.4 ; 108.67,75.27 v1(109.22,75.82) ; v1(109.22,75.82) 108.67,76.37 ; v1(109.22,75.82) 109.77,75.27 ; v1(109.22,75.82) 109.77,76.37 ; v1(48.26,101.78) 48.81,102.33 ; v1(48.26,101.78) 47.71,102.33 ; v1(48.26,101.78) 48.81,101.23 ; v1(48.26,101.78) 47.71,101.23 ; 73.11,91.62 v1(73.66,92.18) ; v1(73.66,92.18) 74.21,92.73 ; v1(73.66,92.18) 74.21,91.62 ; v1(73.66,92.18) 73.11,92.73 ; J3.33 13.63,16.85 ; J3.33 11.77,18.71 ; J3.33 13.63,18.71 ; J3.33 11.77,16.85 ; v1(51.56,4.5) 52.11,5.05 ; v1(51.56,4.5) 51.01,3.94 ; v1(51.56,4.5) 51.01,5.05 ; v1(51.56,4.5) 52.11,3.94 ; 85.17,89.88 v1(85.73,89.33) ; v1(85.73,89.33) 86.28,89.88 ; v1(85.73,89.33) 86.28,88.78 ; v1(85.73,89.33) 85.17,88.78 ; v1(33.02,39.7) 33.57,39.15 ; v1(33.02,39.7) 32.47,40.25 ; v1(33.02,39.7) 33.57,40.25 ; v1(33.02,39.7) 32.47,39.15 ; 26.75,56.41 v1(27.3,55.86) ; v1(27.3,55.86) 27.86,56.41 ; v1(27.3,55.86) 26.75,55.3 ; v1(27.3,55.86) 27.86,55.3 ; 80.47,35.44 v1(81.02,35.99) ; v1(81.02,35.99) 81.57,36.54 ; v1(81.02,35.99) 80.47,36.54 ; v1(81.92,82.3) 82.47,81.74 ; v1(81.92,82.3) 81.36,81.74 ; v1(81.92,82.3) 82.47,82.85 ; v1(81.92,82.3) 81.36,82.85 ; 193,48.51 v1(193.55,47.96) ; v1(193.55,47.96) 193,47.4 ; v1(193.55,47.96) 194.1,48.51 ; v1(193.55,47.96) 194.1,47.4 ; 83.9,96.03 v1(84.45,95.48) ; v1(84.45,95.48) 83.9,94.93 ; v1(84.45,95.48) 85.01,96.03 ; v1(84.45,95.48) 85.01,94.93 ; 21.67,29.9 v1(22.22,30.45) ; v1(22.22,30.45) 22.78,31.01 ; v1(22.22,30.45) 22.78,29.9 ; v1(22.22,30.45) 21.67,31.01 ; 32.47,77.73 v1(33.02,78.28) ; v1(33.02,78.28) 33.57,77.73 ; v1(33.02,78.28) 33.57,78.83 ; v1(33.02,78.28) 32.47,78.83 ; v1(18.41,39.7) 18.97,39.15 ; v1(18.41,39.7) 18.97,40.25 ; v1(18.41,39.7) 17.86,40.25 ; v1(18.41,39.7) 17.86,39.15 ; v1(105.41,69.6) 105.96,69.04 ; v1(105.41,69.6) 104.86,69.04 ; v1(105.41,69.6) 105.96,70.15 ; v1(105.41,69.6) 104.86,70.15 ; v1(66.34,90.8) 66.9,90.25 ; v1(66.34,90.8) 65.79,90.25 ; v1(66.34,90.8) 66.9,91.36 ; v1(66.34,90.8) 65.79,91.36 ; J3.3 8.55,23.79 ; J3.3 6.69,23.79 ; J3.3 8.55,21.93 ; J3.3 6.69,21.93 ; 85.17,75.44 v1(85.73,76) ; v1(85.73,76) 85.17,76.55 ; v1(85.73,76) 86.28,75.44 ; v1(85.73,76) 86.28,76.55 ; 107.4,99.23 v1(107.95,98.68) ; v1(107.95,98.68) 108.5,98.13 ; v1(107.95,98.68) 107.4,98.13 ; v1(107.95,98.68) 108.5,99.23 ; 104.86,95.08 v1(105.41,95.63) ; v1(105.41,95.63) 104.86,96.18 ; v1(105.41,95.63) 105.96,95.08 ; v1(105.41,95.63) 105.96,96.18 ; 21.67,90.74 v1(22.22,91.29) 22.78,90.74 ; J3.1 8.86,19.02 ; J3.1 6.38,19.02 ; J3.1 6.38,16.54 ; J3.1 8.86,16.54 ; 28.66,61.09 v1(29.21,61.65) ; v1(29.21,61.65) 28.66,62.2 ; v1(29.21,61.65) 29.76,62.2 ; v1(29.21,61.65) 29.76,61.09 ; 31.83,101.54 v1(32.39,100.99) ; v1(32.39,100.99) 32.94,101.54 ; v1(32.39,100.99) 31.83,100.44 ; v1(32.39,100.99) 32.94,100.44 ; v1(22.22,78.28) 22.78,78.83 ; v1(22.22,78.28) 21.67,78.83 ; v1(22.22,78.28) 21.67,77.73 ; v1(195.35,12.37) 195.9,11.82 ; v1(195.35,12.37) 195.9,12.92 ; v1(195.35,12.37) 194.8,12.92 ; v1(195.35,12.37) 194.8,11.82 ; 183.6,87.15 v1(184.15,87.71) ; v1(184.15,87.71) 183.6,88.26 ; v1(184.15,87.71) 184.7,87.15 ; v1(184.15,87.71) 184.7,88.26 ; 25.11,100.67 U18.5 ; U18.5 26.96,100.67 ; U18.5 26.96,102.53 ; U18.5 25.11,102.53 ; v1(105.41,108.97) 105.96,108.41 ; v1(105.41,108.97) 105.96,109.52 ; v1(105.41,108.97) 104.86,109.52 ; v1(105.41,108.97) 104.86,108.41 ; 32.47,30.85 v1(33.02,30.3) ; v1(33.02,30.3) 32.47,29.75 ; v1(33.02,30.3) 33.57,29.75 ; v1(79.22,56.01) 79.78,56.56 ; v1(79.22,56.01) 78.67,56.56 ; v1(79.22,56.01) 78.67,55.46 ; v1(79.22,56.01) 79.78,55.46 ; 85.3,45.3 U22.4 ; U22.4 85.3,47.16 ; U22.4 87.16,45.3 ; U22.4 87.16,47.16 ; 136.53,73.16 v1(137.08,73.71) ; v1(137.08,73.71) 137.64,73.16 ; v1(137.08,73.71) 136.53,74.26 ; v1(137.08,73.71) 137.64,74.26 ; 26.5,68.43 v1(27.05,68.99) ; v1(27.05,68.99) 26.5,69.54 ; v1(27.05,68.99) 27.6,69.54 ; v1(27.05,68.99) 27.6,68.43 ; 193,56.29 v1(193.55,56.85) ; v1(193.55,56.85) 194.1,56.29 ; v1(193.55,56.85) 194.1,57.4 ; v1(193.55,56.85) 193,57.4 ; v1(184.15,94.69) 184.7,95.24 ; v1(184.15,94.69) 184.7,94.14 ; v1(184.15,94.69) 183.6,94.14 ; v1(184.15,94.69) 183.6,95.24 ; 17.86,29.75 v1(18.41,30.3) ; v1(18.41,30.3) 18.97,29.75 ; v1(18.41,30.3) 18.97,30.85 ; v1(18.41,30.3) 17.86,30.85 ; v1(40.77,4.5) 41.32,5.05 ; v1(40.77,4.5) 41.32,3.94 ; v1(40.77,4.5) 40.22,3.94 ; v1(40.77,4.5) 40.22,5.05 ; v1(54.23,17.58) 54.78,17.02 ; v1(54.23,17.58) 54.78,18.13 ; v1(54.23,17.58) 53.68,18.13 ; v1(54.23,17.58) 53.68,17.02 ; 26.75,81.19 v1(27.3,81.74) ; v1(27.3,81.74) 27.86,81.19 ; v1(27.3,81.74) 27.86,82.29 ; v1(184.15,58.75) 184.7,59.3 ; v1(184.15,58.75) 183.6,59.3 ; v1(184.15,58.75) 184.7,58.2 ; v1(184.15,58.75) 183.6,58.2 ; 21.67,40.41 v1(22.22,39.85) ; v1(22.22,39.85) 22.78,39.3 ; v1(22.22,39.85) 22.78,40.41 ; v1(22.22,39.85) 21.67,39.3 ; v1(25.91,44.22) 26.46,43.67 ; v1(25.91,44.22) 25.36,44.77 ; v1(25.91,44.22) 26.46,44.77 ; v1(25.91,44.22) 25.36,43.67 ; v1(107.95,82.14) 108.5,81.59 ; v1(107.95,82.14) 108.5,82.7 ; v1(107.95,82.14) 107.4,82.7 ; v1(107.95,82.14) 107.4,81.59 ; v1(84.45,69.6) 85.01,69.04 ; v1(84.45,69.6) 83.9,70.15 ; v1(84.45,69.6) 83.9,69.04 ; v1(84.45,69.6) 85.01,70.15 ; 147.35,22.33 v1(147.9,22.88) ; v1(147.9,22.88) 148.45,23.43 ; v1(147.9,22.88) 148.45,22.33 ; v1(147.9,22.88) 147.35,23.43 ; v1(42.8,40.87) 43.35,41.42 ; v1(42.8,40.87) 42.25,40.32 ; v1(42.8,40.87) 42.25,41.42
  BOTTOM w0.4: v1(49.43,74.93) C4.2 ; v1(73.3,78.44) 73.3,77.42 73.4,77.32 C1.2 ; v1(73.66,105.51) C7.2 ; v1(73.66,92.18) C8.2
GND_EARTH: length 119.3
  TOP w0.4: S1.1 v1(144.1,22.88) ; J1.5 J1.3 130.09,28.61 v1(130.09,24.68) ; J2.5 J2.3 130.69,7.51 C13.2 ; J1.4 J1.2
  GND w0.3: v1(130.09,24.68) 130.64,24.13 ; v1(130.09,24.68) 129.53,24.13 ; v1(130.09,24.68) 129.53,25.23 ; v1(130.09,24.68) 130.64,25.23 ; 132.67,33.65 J1.4 ; J1.4 132.67,36.19 ; J1.4 135.21,36.19 ; J1.4 135.21,33.65 ; 127.79,10.41 J2.3 ; J2.3 130.33,10.41 ; J2.3 130.33,7.87 ; J2.3 127.79,7.87 ; J2.5 135.41,7.87 ; J2.5 132.87,7.87 ; J2.5 135.41,10.41 ; J2.5 132.87,10.41 ; J2.4 135.41,15.49 ; J2.4 135.41,12.95 ; J2.4 132.87,15.49 ; J2.4 132.87,12.95 ; 127.59,31.11 J1.3 ; J1.3 130.13,31.11 ; J1.3 127.59,28.57 ; J1.3 130.13,28.57 ; 143.55,22.33 v1(144.1,22.88) ; v1(144.1,22.88) 143.55,23.43 ; v1(144.1,22.88) 144.65,22.33 ; v1(144.1,22.88) 144.65,23.43 ; J1.2 130.13,36.19 ; J1.2 130.13,33.65 ; J1.2 127.59,33.65 ; J1.2 127.59,36.19 ; J1.5 135.21,28.57 ; J1.5 132.67,31.11 ; J1.5 132.67,28.57 ; J1.5 135.21,31.11 ; J2.2 130.33,15.49 ; J2.2 127.79,12.95 ; J2.2 127.79,15.49 ; J2.2 130.33,12.95
  BOTTOM w0.4: J1.5 133.86,29.84 131.7,27.68 131.7,18.7 133.82,16.58 133.82,14.54 J2.4 J2.5 ; J1.3 J1.2
V12N: length 247.8
  TOP w0.4: v1(98.45,21.29) 98.45,21.29 98.45,14.03 ; 96.6,34.73 110.92,34.73 111.94,33.71 111.94,33.64 113.16,32.41 U2_1.7 ; 96.6,34.73 96.6,37.85 91.52,42.93 58.91,42.93 56.95,44.89 41.35,44.89 38.23,41.77 38.23,40.4 30.61,32.78 19.89,32.78 17.6,30.49 v1(17.6,26.75) ; 96.6,34.73 96.6,34.4 96.32,34.4 96.32,31.93 ; 113.78,11.71 111.77,11.71 109.45,14.03 98.45,14.03 ; J3.32 J3.31 ; U3_1.4 96,31.6 96.32,31.93 ; 96.32,31.93 v1(100.56,31.93) ; 98.45,14.03 96.3,11.88 96.3,9.18
  BOTTOM w0.4: v1(100.56,31.93) 101.53,30.96 101.53,24.36 v1(98.45,21.29) ; J3.31 3.82,90.18 3.82,29.92 6.99,26.75 17.6,26.75 v1(17.6,26.75)
VCC: length 470
  TOP w0.4: U27.34 183.42,56.85 183.42,56.85 v1(184.15,56.85) ; v1(31.11,36.25) U16.28 ; v1(42.8,26.59) U21.20 ; v1(109.22,108.97) U6.24 ; v1(24.26,65.1) 24.26,64.92 24.13,64.8 U14.39 ; v1(20.32,26.85) U16.4 ; v1(31.11,26.85) U16.21 ; v1(184.15,92.79) 183.42,92.79 183.42,92.79 U26.34 ; U1_2.2 80.12,14.01 80.13,14.02 v1(81.4,14.02) ; U14.10 24.13,55.4 24.26,55.52 v1(24.26,55.7) ; v1(27.3,61.6) U14.34 ; v1(78.2,5.13) 79.47,5.13 79.48,5.12 U1_2.9 ; U20.20 43.34,39.02 43.36,39.03 v1(43.36,39.83) ; v1(75.67,56.01) C6.1 ; v1(28.85,77.52) 29.21,77.88 U15.18 ; v1(24.26,81.74) 24.26,81.56 24.13,81.43 U15.10 ; U26.4 184.15,85.8 v1(184.15,85.8) 184.15,85.8 U26.45 ; v1(32.39,104.8) C20.1 ; v1(27.3,91.13) U15.34 ; v1(37.29,92.07) U7.38 ; U27.28 183.42,60.66 v1(184.15,60.66) ; v1(59.69,101.78) U7.17 ; U25.20 203.72,23.79 203.73,23.8 v1(204.55,23.8) ; v1(82.86,38.68) 81.3,38.68 C1_1.1 ; U26.21 192.82,96.6 192.82,96.6 v1(193.55,96.6) ; U27.21 192.82,60.66 192.82,60.66 v1(193.55,60.66) ; v1(77.9,25.83) 79.17,25.83 79.18,25.82 U1_1.9 ; v1(42.8,50.22) U19.20 ; v1(85.73,95.48) U2.24 ; U27.45 184.15,49.86 v1(184.15,49.86) 184.15,49.86 U27.4 ; C5.1 73.61,64.18 v1(73.61,63.07) ; v1(109.22,95.63) U102.24 ; v1(27.3,36.25) U16.34 ; v1(31.11,55.7) U14.21 ; v1(20.32,55.7) U14.4 ; U8.5 140.1,52.72 140.09,52.73 v1(139.29,52.73) ; v1(180.67,53.67) 182.41,53.67 U27.39 U27.10 ; v1(80.03,18.44) 81.24,18.44 81.6,18.08 C1_2.1 ; v1(81.36,35.03) 81.05,34.72 79.83,34.72 79.82,34.71 U1_1.2 ; v1(29.21,52.25) U14.18 ; v1(109.22,82.14) U101.24 ; v1(28.07,18.52) C18.1 ; U26.10 U26.39 180.72,89.61 v1(180.67,89.66) ; v1(107.95,72.77) U101.8 ; v1(107.95,89.15) U102.8 ; v1(85.73,108.97) U4.24 ; v1(46.99,69.67) U7.59 ; v1(29.21,30.3) U16.18 ; v1(109.22,69.6) U3.24 ; v1(24.26,36.25) 24.26,36.42 24.13,36.55 U16.39 ; v1(20.32,61.65) U14.45 ; v1(20.32,36.14) U16.45 ; v1(66.34,79.38) U7.80 ; v1(84.45,99.44) U4.8 ; v1(31.11,87.68) U15.28 ; v1(85.73,69.6) U5.24 ; v1(146.28,85.14) 145.45,85.14 145.45,85.13 U24.20 ; U26.18 192.82,94.69 192.82,94.69 v1(193.55,94.69) ; v1(107.95,102.49) U6.8 ; v1(15.88,56.03) C2.1 ; v1(27.05,74.78) C19.1 ; v1(31.11,81.74) U15.21 ; v1(20.32,78.28) U15.4 ; v1(184.15,96.6) 183.42,96.6 183.42,96.6 U26.28 ; v1(20.32,91.13) U15.45 ; U27.18 192.82,58.75 192.82,58.75 v1(193.55,58.75) ; v1(25.91,50.16) C17.1 ; v1(84.45,89.33) U2.8 ; v1(25.32,91.13) 24.13,91.13 U15.39 ; v1(85.73,82.3) U1.24 ; v1(31.11,61.65) U14.28 ; v1(84.45,76) U1.8 ; v1(24.26,30.3) 24.26,30.12 24.13,30 U16.10 ; v1(84.45,63.12) U5.8 ; v1(107.95,63.12) U3.8 ; v1(40.26,38.96) C3.1
  VCC w0.3: 65.26,28.12 L2_1.1 ; L2_1.1 66.94,26.44 ; L2_1.1 66.94,28.12 ; L2_1.1 65.26,26.44 ; U18.8 19.34,100.67 ; U18.8 17.49,100.67 ; U18.8 19.34,102.53 ; U18.8 17.49,102.53 ; 45.32,74.38 v1(45.87,74.93) ; v1(45.87,74.93) 46.42,74.38 ; v1(45.87,74.93) 46.42,75.48 ; v1(45.87,74.93) 45.32,75.48 ; v1(85.73,69.6) 86.28,70.15 ; v1(85.73,69.6) 86.28,69.04 ; v1(85.73,69.6) 85.17,69.04 ; v1(85.73,69.6) 85.17,70.15 ; v1(25.32,91.13) 25.88,90.58 ; v1(25.32,91.13) 25.88,91.69 ; v1(25.32,91.13) 24.77,90.58 ; v1(25.32,91.13) 24.77,91.69 ; 28.3,78.07 v1(28.85,77.52) ; v1(28.85,77.52) 29.41,78.07 ; v1(28.85,77.52) 28.3,76.97 ; v1(28.85,77.52) 29.41,76.97 ; 30.56,62.2 v1(31.11,61.65) ; v1(31.11,61.65) 31.67,62.2 ; v1(31.11,61.65) 31.67,61.09 ; v1(31.11,61.65) 30.56,61.09 ; v1(109.22,108.97) 109.77,108.41 ; v1(109.22,108.97) 109.77,109.52 ; v1(109.22,108.97) 108.67,108.41 ; v1(109.22,108.97) 108.67,109.52 ; 183.6,50.41 v1(184.15,49.86) ; v1(184.15,49.86) 183.6,49.31 ; v1(184.15,49.86) 184.7,49.31 ; v1(184.15,49.86) 184.7,50.41 ; 19.77,78.83 v1(20.32,78.28) ; v1(20.32,78.28) 19.77,77.73 ; v1(20.32,78.28) 20.87,77.73 ; v1(20.32,78.28) 20.87,78.83 ; J3.62 13.63,92.37 ; J3.62 11.77,90.51 ; J3.62 11.77,92.37 ; J3.62 13.63,90.51 ; v1(204.55,23.8) 205.1,23.25 ; v1(204.55,23.8) 203.99,24.35 ; v1(204.55,23.8) 205.1,24.35 ; v1(204.55,23.8) 203.99,23.25 ; 65.79,78.82 v1(66.34,79.38) ; v1(66.34,79.38) 65.79,79.93 ; v1(66.34,79.38) 66.9,79.93 ; v1(66.34,79.38) 66.9,78.82 ; v1(109.22,69.6) 109.77,70.15 ; v1(109.22,69.6) 108.67,69.04 ; v1(109.22,69.6) 108.67,70.15 ; v1(109.22,69.6) 109.77,69.04 ; 73.11,108.52 v1(73.66,109.07) ; v1(73.66,109.07) 74.21,108.52 ; v1(73.66,109.07) 74.21,109.62 ; v1(73.66,109.07) 73.11,109.62 ; 193,94.14 v1(193.55,94.69) ; v1(193.55,94.69) 194.1,95.24 ; v1(193.55,94.69) 194.1,94.14 ; v1(193.55,94.69) 193,95.24 ; 28.66,51.7 v1(29.21,52.25) ; v1(29.21,52.25) 29.76,51.7 ; v1(29.21,52.25) 28.66,52.8 ; v1(29.21,52.25) 29.76,52.8 ; v1(20.32,36.14) 20.87,36.7 ; v1(20.32,36.14) 19.77,36.7 ; v1(20.32,36.14) 20.87,35.59 ; v1(20.32,36.14) 19.77,35.59 ; 108.67,81.59 v1(109.22,82.14) ; v1(109.22,82.14) 109.77,82.7 ; v1(109.22,82.14) 108.67,82.7 ; v1(109.22,82.14) 109.77,81.59 ; v1(20.32,61.65) 20.87,61.09 ; v1(20.32,61.65) 19.77,62.2 ; v1(20.32,61.65) 20.87,62.2 ; v1(73.61,63.07) 74.16,63.62 ; v1(73.61,63.07) 73.06,62.52 ; v1(73.61,63.07) 73.06,63.62 ; v1(73.61,63.07) 74.16,62.52 ; v1(184.15,60.66) 184.7,61.21 ; v1(184.15,60.66) 184.7,60.1 ; v1(184.15,60.66) 183.6,61.21 ; v1(184.15,60.66) 183.6,60.1 ; 183.6,85.25 v1(184.15,85.8) ; v1(184.15,85.8) 184.7,85.25 ; v1(184.15,85.8) 183.6,86.35 ; v1(184.15,85.8) 184.7,86.35 ; 85.17,96.03 v1(85.73,95.48) ; v1(85.73,95.48) 85.17,94.93 ; v1(85.73,95.48) 86.28,94.93 ; v1(85.73,95.48) 86.28,96.03 ; CR3.2 75.22,51.09 ; CR3.2 73.37,49.24 ; CR3.2 73.37,51.09 ; CR3.2 75.22,49.24 ; v1(75.67,56.01) 76.22,55.46 ; v1(75.67,56.01) 75.12,55.46 ; v1(75.67,56.01) 75.12,56.56 ; v1(75.67,56.01) 76.22,56.56 ; 83.9,98.89 v1(84.45,99.44) ; v1(84.45,99.44) 83.9,99.99 ; v1(84.45,99.44) 85.01,98.89 ; v1(84.45,99.44) 85.01,99.99 ; 25.36,49.61 v1(25.91,50.16) ; v1(25.91,50.16) 26.46,50.72 ; v1(25.91,50.16) 25.36,50.72 ; v1(25.91,50.16) 26.46,49.61 ; v1(24.26,55.7) 24.81,55.15 ; v1(24.26,55.7) 24.81,56.25 ; v1(24.26,55.7) 23.7,56.25 ; v1(24.26,55.7) 23.7,55.15 ; L2_2.1 67.24,5.74 ; L2_2.1 67.24,7.42 ; L2_2.1 65.56,5.74 ; L2_2.1 65.56,7.42 ; 108.67,96.18 v1(109.22,95.63) ; v1(109.22,95.63) 108.67,95.08 ; v1(109.22,95.63) 109.77,96.18 ; v1(109.22,95.63) 109.77,95.08 ; 67.02,51.09 CR2.2 ; CR2.2 68.87,49.24 ; CR2.2 68.87,51.09 ; CR2.2 67.02,49.24 ; 46.44,70.22 v1(46.99,69.67) ; v1(46.99,69.67) 46.44,69.12 ; v1(46.99,69.67) 47.54,70.22 ; v1(46.99,69.67) 47.54,69.12 ; 183.6,57.4 v1(184.15,56.85) ; v1(184.15,56.85) 184.7,56.29 ; v1(184.15,56.85) 184.7,57.4 ; v1(184.15,56.85) 183.6,56.29 ; 6.69,92.37 J3.30 ; J3.30 6.69,90.51 ; J3.30 8.55,90.51 ; J3.30 8.55,92.37 ; v1(42.8,26.59) 43.35,27.15 ; v1(42.8,26.59) 42.25,26.04 ; v1(42.8,26.59) 43.35,26.04 ; v1(42.8,26.59) 42.25,27.15 ; v1(184.15,92.79) 184.7,93.34 ; v1(184.15,92.79) 184.7,92.23 ; v1(184.15,92.79) 183.6,93.34 ; v1(184.15,92.79) 183.6,92.23 ; J3.29 8.55,89.83 ; J3.29 6.69,89.83 ; J3.29 6.69,87.97 ; J3.29 8.55,87.97 ; 60.67,51.09 CR1.2 ; CR1.2 60.67,49.24 ; CR1.2 62.52,51.09 ; CR1.2 62.52,49.24 ; 183.6,96.04 v1(184.15,96.6) ; v1(184.15,96.6) 183.6,97.15 ; v1(184.15,96.6) 184.7,96.04 ; v1(184.15,96.6) 184.7,97.15 ; v1(180.67,89.66) 181.22,90.21 ; v1(180.67,89.66) 180.12,90.21 ; v1(180.67,89.66) 181.22,89.11 ; v1(180.67,89.66) 180.12,89.11 ; 23.7,65.65 v1(24.26,65.1) ; v1(24.26,65.1) 23.7,64.55 ; v1(24.26,65.1) 24.81,65.65 ; v1(24.26,65.1) 24.81,64.55 ; 193,58.2 v1(193.55,58.75) ; v1(193.55,58.75) 194.1,58.2 ; v1(193.55,58.75) 193,59.3 ; v1(193.55,58.75) 194.1,59.3 ; v1(32.39,104.8) 32.94,105.35 ; v1(32.39,104.8) 31.83,105.35 ; v1(32.39,104.8) 32.94,104.25 ; v1(32.39,104.8) 31.83,104.25 ; 36.73,91.52 v1(37.29,92.07) ; v1(37.29,92.07) 37.84,92.63 ; v1(37.29,92.07) 37.84,91.52 ; v1(37.29,92.07) 36.73,92.63 ; v1(31.11,26.85) 31.67,26.3 ; v1(31.11,26.85) 30.56,27.4 ; v1(31.11,26.85) 31.67,27.4 ; v1(31.11,26.85) 30.56,26.3 ; 80.81,34.48 v1(81.36,35.03) 81.91,35.58 ; v1(81.4,14.02) 81.95,14.57 ; v1(81.4,14.02) 80.85,13.47 ; v1(81.4,14.02) 80.85,14.57 ; v1(81.4,14.02) 81.95,13.47 ; 107.4,73.32 v1(107.95,72.77) ; v1(107.95,72.77) 108.5,73.32 ; v1(107.95,72.77) 108.5,72.22 ; v1(107.95,72.77) 107.4,72.22 ; v1(139.29,52.73) 139.85,52.18 ; v1(139.29,52.73) 138.74,53.28 ; v1(139.29,52.73) 138.74,52.18 ; v1(139.29,52.73) 139.85,53.28 ; 30.56,56.25 v1(31.11,55.7) ; v1(31.11,55.7) 30.56,55.15 ; v1(31.11,55.7) 31.67,55.15 ; v1(31.11,55.7) 31.67,56.25 ; 77.35,26.38 v1(77.9,25.83) ; v1(77.9,25.83) 78.45,26.38 ; v1(77.9,25.83) 78.45,25.28 ; v1(77.9,25.83) 77.35,25.28 ; v1(107.95,89.15) 108.5,89.71 ; v1(107.95,89.15) 107.4,88.6 ; v1(107.95,89.15) 108.5,88.6 ; v1(31.11,87.68) 31.67,87.13 ; v1(31.11,87.68) 30.56,87.13 ; v1(31.11,87.68) 31.67,88.23 ; v1(31.11,87.68) 30.56,88.23 ; 193,97.15 v1(193.55,96.6) ; v1(193.55,96.6) 194.1,96.04 ; v1(193.55,96.6) 193,96.04 ; v1(193.55,96.6) 194.1,97.15 ; v1(85.73,82.3) 86.28,82.85 ; v1(85.73,82.3) 85.17,82.85 ; v1(85.73,82.3) 86.28,81.74 ; v1(85.73,82.3) 85.17,81.74 ; 42.25,49.66 v1(42.8,50.22) ; v1(42.8,50.22) 42.25,50.77 ; v1(42.8,50.22) 43.35,50.77 ; v1(42.8,50.22) 43.35,49.66 ; v1(73.66,95.73) 74.21,96.28 ; v1(73.66,95.73) 73.11,96.28 ; v1(73.66,95.73) 74.21,95.18 ; v1(73.66,95.73) 73.11,95.18 ; 26.75,62.15 v1(27.3,61.6) ; v1(27.3,61.6) 27.86,61.04 ; v1(27.3,61.6) 27.86,62.15 ; v1(20.32,26.85) 20.87,27.4 ; v1(20.32,26.85) 20.87,26.3 ; v1(20.32,26.85) 19.77,26.3 ; v1(20.32,26.85) 19.77,27.4 ; 107.4,101.94 v1(107.95,102.49) ; v1(107.95,102.49) 107.4,103.04 ; v1(107.95,102.49) 108.5,101.94 ; v1(107.95,102.49) 108.5,103.04 ; CR4.2 82.21,51.09 ; CR4.2 80.35,49.24 ; CR4.2 80.35,51.09 ; CR4.2 82.21,49.24 ; v1(31.11,36.25) 31.67,35.69 ; v1(31.11,36.25) 30.56,36.8 ; v1(31.11,36.25) 30.56,35.69 ; v1(31.11,36.25) 31.67,36.8 ; v1(73.61,81.99) 74.16,81.44 ; v1(73.61,81.99) 73.06,81.44 ; v1(73.61,81.99) 73.06,82.54 ; v1(73.61,81.99) 74.16,82.54 ; 30.56,81.19 v1(31.11,81.74) ; v1(31.11,81.74) 31.67,82.29 ; v1(31.11,81.74) 31.67,81.19 ; v1(84.45,89.33) 85.01,88.78 ; v1(84.45,89.33) 85.01,89.88 ; v1(84.45,89.33) 83.9,88.78 ; v1(84.45,89.33) 83.9,89.88 ; 26.5,74.23 v1(27.05,74.78) ; v1(27.05,74.78) 27.6,75.33 ; v1(27.05,74.78) 26.5,75.33 ; v1(27.05,74.78) 27.6,74.23 ; v1(180.67,53.67) 181.22,54.22 ; v1(180.67,53.67) 180.12,53.12 ; v1(180.67,53.67) 180.12,54.22 ; v1(180.67,53.67) 181.22,53.12 ; 19.77,90.58 v1(20.32,91.13) 20.87,90.58 ; 92.92,52.92 U22.8 ; U22.8 94.78,52.92 ; U22.8 92.92,54.78 ; U22.8 94.78,54.78 ; v1(15.88,56.03) 16.43,55.48 ; v1(15.88,56.03) 15.32,55.48 ; v1(15.88,56.03) 15.32,56.58 ; v1(15.88,56.03) 16.43,56.58 ; v1(78.2,5.13) 78.75,5.68 ; v1(78.2,5.13) 77.65,4.58 ; v1(78.2,5.13) 77.65,5.68 ; v1(78.2,5.13) 78.75,4.58 ; 59.14,101.23 v1(59.69,101.78) ; v1(59.69,101.78) 60.24,101.23 ; v1(59.69,101.78) 60.24,102.33 ; v1(59.69,101.78) 59.14,102.33 ; v1(107.95,63.12) 108.5,62.57 ; v1(107.95,63.12) 108.5,63.67 ; v1(107.95,63.12) 107.4,63.67 ; v1(107.95,63.12) 107.4,62.57 ; 145.73,84.59 v1(146.28,85.14) ; v1(146.28,85.14) 146.83,85.69 ; v1(146.28,85.14) 146.83,84.59 ; v1(146.28,85.14) 145.73,85.69 ; v1(29.21,30.3) 29.76,29.75 ; v1(29.21,30.3) 28.66,30.85 ; v1(29.21,30.3) 29.76,30.85 ; v1(29.21,30.3) 28.66,29.75 ; 23.7,35.69 v1(24.26,36.25) ; v1(24.26,36.25) 23.7,36.8 ; v1(24.26,36.25) 24.81,36.8 ; 37.81,62.57 U17.24 ; U17.24 39.66,62.57 ; U17.24 39.66,64.43 ; U17.24 37.81,64.43 ; 83.9,62.57 v1(84.45,63.12) ; v1(84.45,63.12) 85.01,63.67 ; v1(84.45,63.12) 85.01,62.57 ; v1(84.45,63.12) 83.9,63.67 ; U18.7 21.88,102.53 ; U18.7 20.03,100.67 ; U18.7 21.88,100.67 ; U18.7 20.03,102.53 ; 42.81,39.28 v1(43.36,39.83) 43.91,39.28 ; v1(40.26,38.96) 40.81,38.41 ; v1(40.26,38.96) 39.71,39.52 ; v1(40.26,38.96) 40.81,39.52 ; v1(40.26,38.96) 39.71,38.41 ; v1(85.73,108.97) 86.28,109.52 ; v1(85.73,108.97) 85.17,109.52 ; v1(85.73,108.97) 86.28,108.41 ; v1(85.73,108.97) 85.17,108.41 ; v1(24.26,81.74) 24.81,81.19 ; v1(24.26,81.74) 24.81,82.29 ; v1(24.26,81.74) 23.7,81.19 ; v1(24.26,81.74) 23.7,82.29 ; v1(27.3,91.13) 27.86,90.58 ; v1(27.3,91.13) 26.75,90.58 ; v1(27.3,91.13) 26.75,91.69 ; v1(27.3,91.13) 27.86,91.69 ; 82.3,38.13 v1(82.86,38.68) ; v1(82.86,38.68) 83.41,39.24 ; v1(82.86,38.68) 82.3,39.24 ; v1(82.86,38.68) 83.41,38.13 ; 79.48,18.99 v1(80.03,18.44) ; v1(80.03,18.44) 80.59,17.89 ; v1(80.03,18.44) 80.59,18.99 ; v1(80.03,18.44) 79.48,17.89 ; 23.7,29.75 v1(24.26,30.3) ; v1(24.26,30.3) 23.7,30.85 ; v1(24.26,30.3) 24.81,29.75 ; v1(24.26,30.3) 24.81,30.85 ; 19.77,55.15 v1(20.32,55.7) ; v1(20.32,55.7) 19.77,56.25 ; v1(20.32,55.7) 20.87,56.25 ; v1(20.32,55.7) 20.87,55.15 ; 26.75,35.69 v1(27.3,36.25) 26.75,36.8 ; v1(193.55,60.66) 194.1,60.1 ; v1(193.55,60.66) 194.1,61.21 ; v1(193.55,60.66) 193,60.1 ; v1(193.55,60.66) 193,61.21 ; 27.52,17.96 v1(28.07,18.52) ; v1(28.07,18.52) 27.52,19.07 ; v1(28.07,18.52) 28.62,17.96 ; v1(28.07,18.52) 28.62,19.07 ; 83.9,76.55 v1(84.45,76) ; v1(84.45,76) 83.9,75.44 ; v1(84.45,76) 85.01,75.44 ; v1(84.45,76) 85.01,76.55
  BOTTOM w0.4: C1.1 73.61,80.88 v1(73.61,81.99) ; v1(73.66,95.73) C8.1 ; v1(45.87,74.93) C4.1 ; v1(73.66,109.07) C7.1
